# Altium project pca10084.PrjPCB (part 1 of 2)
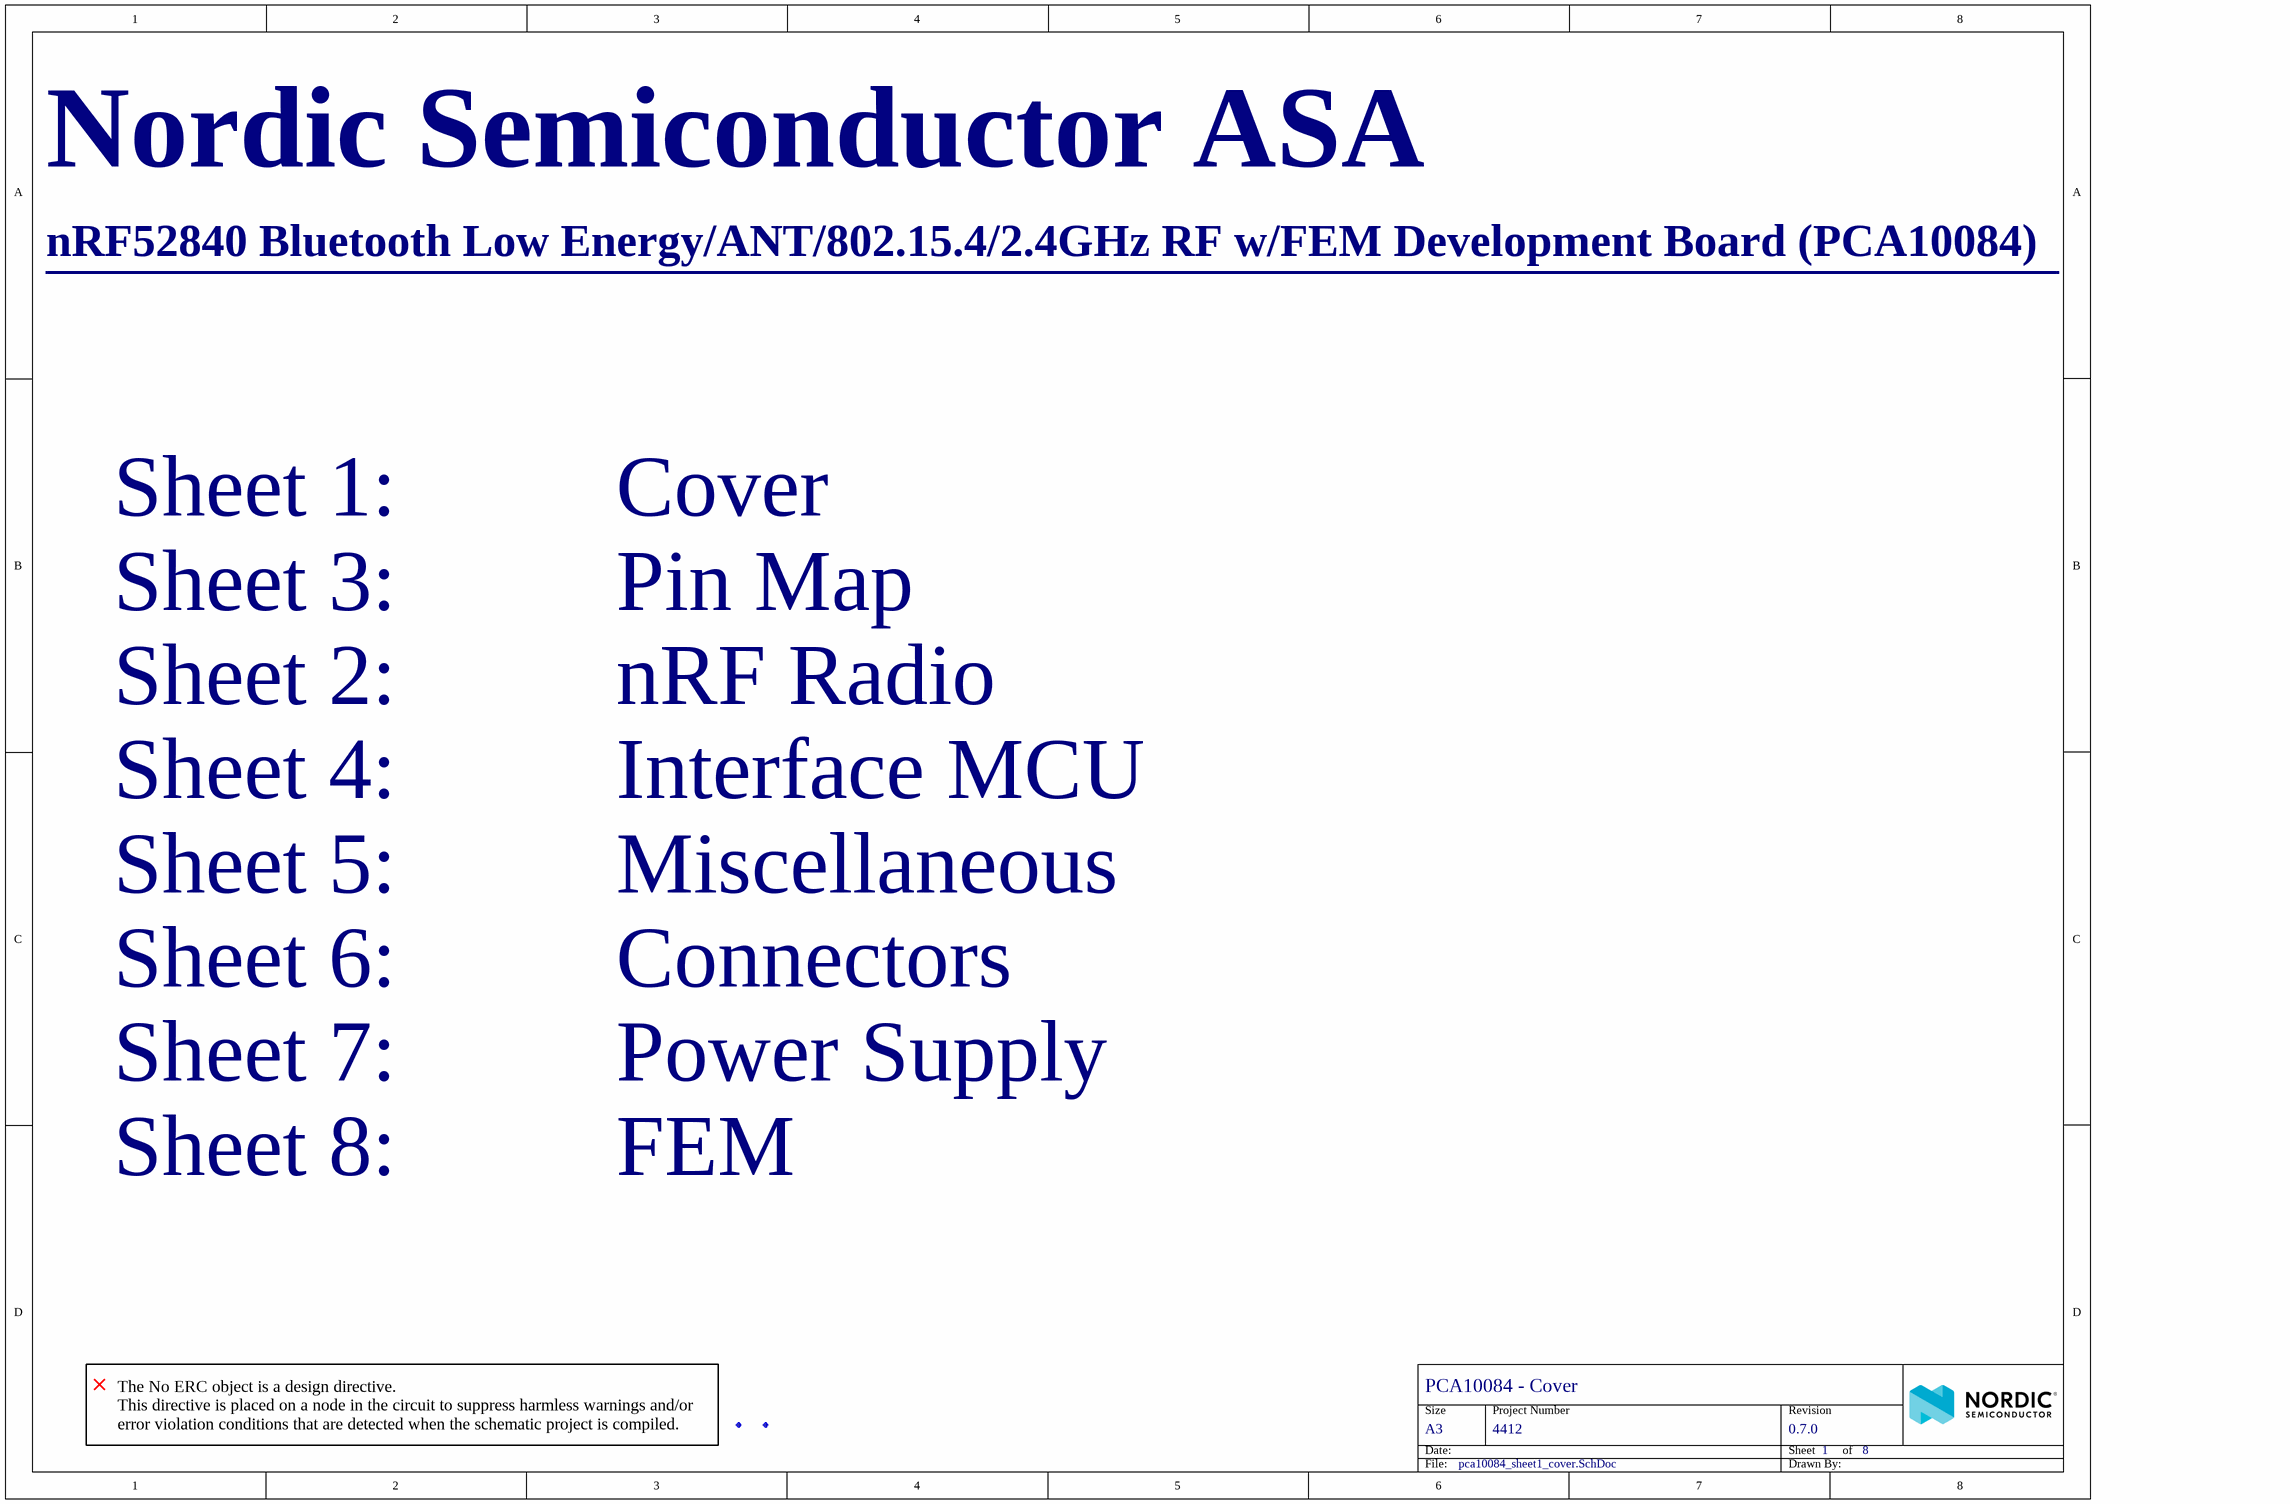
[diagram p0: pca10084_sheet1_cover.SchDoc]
Author: GETR; BoardThickness: 1.6mm; BoardTitle: nRF52840 with SkY66112-11; NrOfLayers: 4; Organization: Nordic Semiconductor; PCAName: PCA10084; PCBNumber: 400339; PCBRevision: 0093GETR; PCBStackup: 4001; ProjectName: Key Customer Support; ProjectNumber: 4412; Revision: 0.7.0; SilkscreenColor: White; SoldermaskColor: Blue; SurfaceFinish: Gold
8 sheets, 403 parts. Net scope: flat (ports and power ports of the same name join across sheets).
Board files: 400339.PcbDoc, 400339_panel.PcbDoc
Sheets:
  pca10084_sheet1_cover.SchDoc
  pca10084_sheet2_nrf52840_mcu.SchDoc
  pca10084_sheet3_pin_map.SchDoc
  pca10084_sheet4_interface_mcu.SchDoc
  pca10084_sheet5_misc.SchDoc
  pca10084_sheet6_connectors.SchDoc
  pca10084_sheet7_power_supply.SchDoc
  pca10084_sheet8_skyworks.SchDoc

## Sheet pca10084_sheet1_cover.SchDoc: PCA10084 - Cover
size A3; Organization: Nordic Semiconductor; DocumentNumber: 1; Revision: 0.7.0; SheetNumber: 1; SheetTotal: 8; Author: GETR; CompanyName: Nordic Semiconductor; DrawnBy: GETR

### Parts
Fid1  Fiducial mark  [Fiducial]  (value not drawn)  (no BOM)
Fid2  Fiducial mark  [Fiducial]  (value not drawn)  (no BOM)

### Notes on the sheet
- Nordic Semiconductor ASA
- nRF52840 Bluetooth Low Energy/ANT/802.15.4/2.4GHz RF w/FEM Development Board (PCA10084)
- __________________________________________________________________
- Sheet 1:          Cover
- Sheet 3:          Pin Map
- Sheet 2:          nRF Radio
- Sheet 4:          Interface MCU
- Sheet 5:          Miscellaneous
- Sheet 6:          Connectors
- Sheet 7:          Power Supply
- Sheet 8:          FEM
- (near Fid1) The No ERC object is a design directive.
  This directive is placed on a node in the circuit to suppress harmless warnings and/or error violation conditions that are detected when the schematic project is compiled.

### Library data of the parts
Fid1 Fid2 = Fid-Mark: Artikkelnr Noca: N.A.

## Sheet pca10084_sheet2_nrf52840_mcu.SchDoc: PCA10084 - nRF52840 MCU
size A3; Organization: Nordic Semiconductor; DocumentNumber: 2; Revision: 0.7.0; SheetNumber: 2; SheetTotal: 8; Author: GETR; CompanyName: Nordic Semiconductor; DrawnBy: GETR
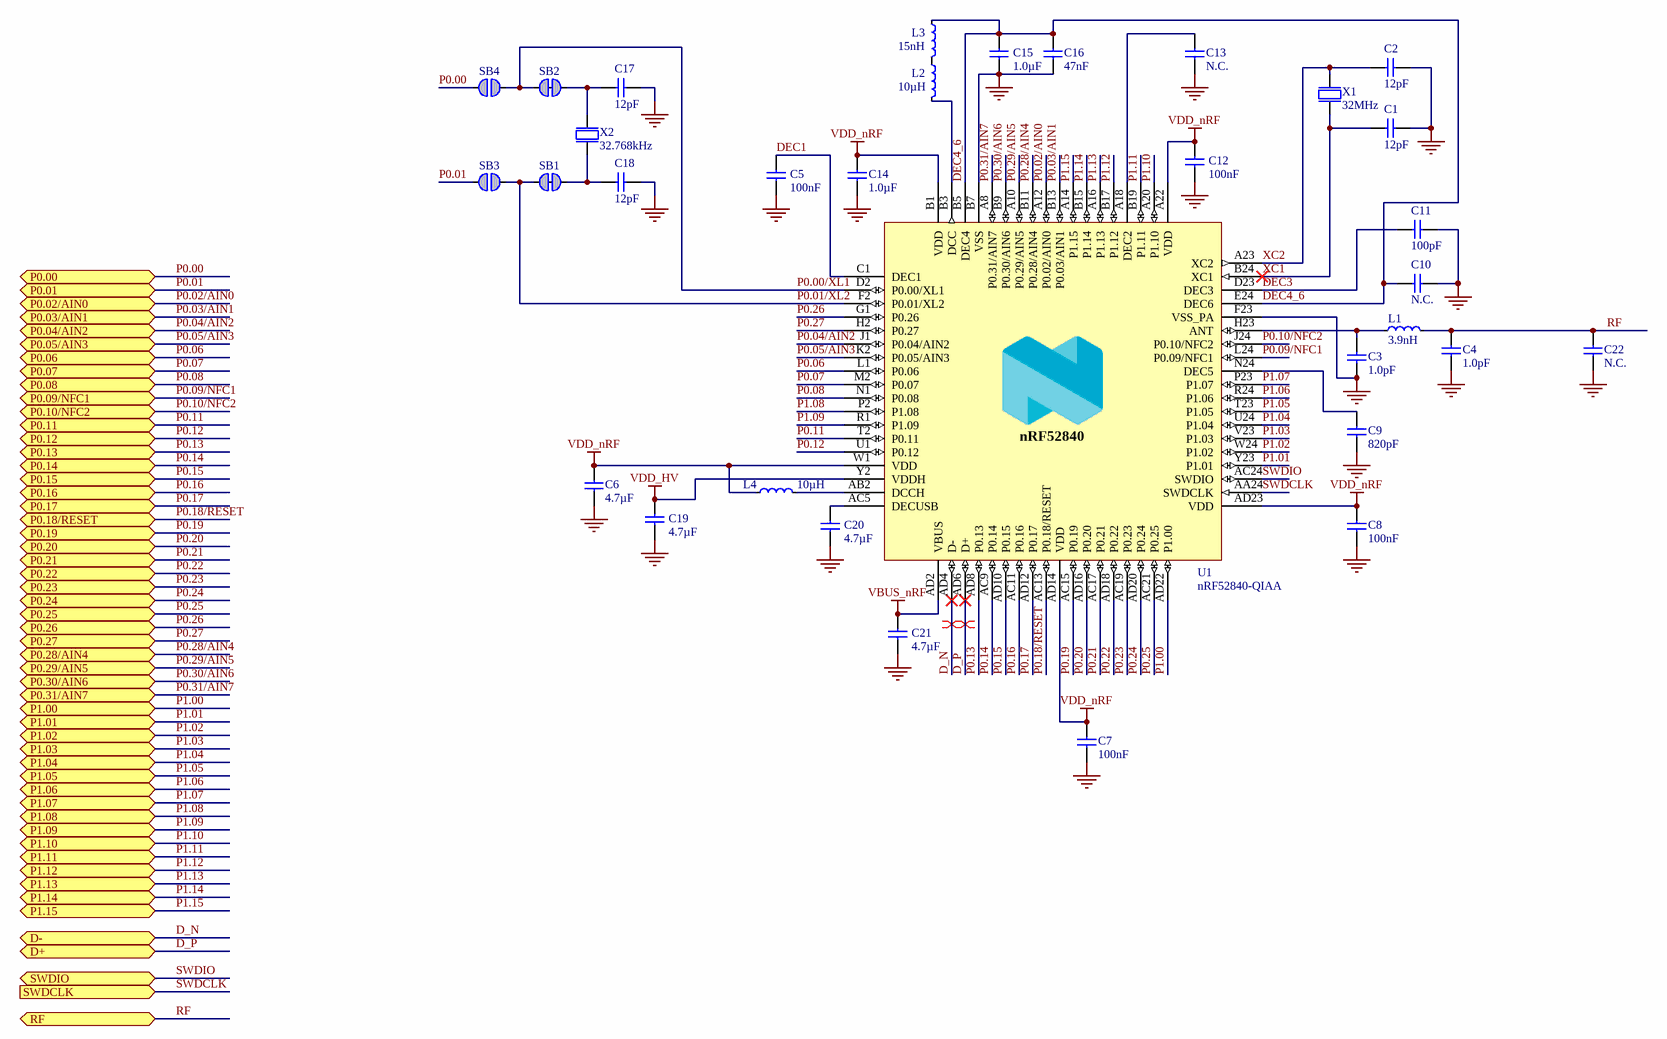
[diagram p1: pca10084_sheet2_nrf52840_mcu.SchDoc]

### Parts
C1  12pF  [CAPC1005X04L]
C2  12pF  [CAPC1005X04L]
C3  1.0pF  [CAPC1005X04L]
C4  1.0pF  [CAPC1005X04L]
C5  100nF  [CAPC1005X04L]
C6  4.7µF  [CAPC1608X06L]
C7  100nF  [CAPC1005X04L]
C8  100nF  [CAPC1005X04L]
C9  820pF  [CAPC1005X04L]
C10  N.C.  [CAPC1005X04L]
C11  100pF  [CAPC1005X04L]
C12  100nF  [CAPC1005X04L]
C13  N.C.  [CAPC1005X04L]
C14  1.0µF  [CAPC1608X06L]
C15  1.0µF  [CAPC1608X06L]
C16  47nF  [CAPC1005X04L]
C17  12pF  [CAPC1005X04L]
C18  12pF  [CAPC1005X04L]
C19  4.7µF  [CAPC1608X06L]
C20  4.7µF  [CAPC1608X06L]
C21  4.7µF  [CAPC1608X06L]
C22  N.C.  [CAPC1005X04L]
L1  3.9nH  [INDC1005X04L]
L2  10µH  [INDC1608X06L]
L3  15nH  [INDC1005X04L]
L4  10µH  [INDC1608X06L]
SB1  Solderbridge  [Solderbridge_Shorted]  (value not drawn)  (net tie, no BOM)
SB2  Solderbridge  [Solderbridge_Shorted]  (value not drawn)  (net tie, no BOM)
SB3  Solderbridge  [Solderbridge]  (value not drawn)  (no BOM)
SB4  Solderbridge  [Solderbridge]  (value not drawn)  (no BOM)
U1  nRF52840-QIAA  [AQFN50P700X700X85_HS-74N]
X1  32MHz  [BT-XTAL_2016]
X2  32.768kHz  [XTAL_3215]

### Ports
D+ (bidir), D- (bidir), P0.00 (bidir), P0.01 (bidir), P0.02/AIN0 (bidir), P0.03/AIN1 (bidir), P0.04/AIN2 (bidir), P0.05/AIN3 (bidir), P0.06 (bidir), P0.07 (bidir), P0.08 (bidir), P0.09/NFC1 (bidir), P0.10/NFC2 (bidir), P0.11 (bidir), P0.12 (bidir), P0.13 (bidir), P0.14 (bidir), P0.15 (bidir), P0.16 (bidir), P0.17 (bidir), P0.18/RESET (bidir), P0.19 (bidir), P0.20 (bidir), P0.21 (bidir), P0.22 (bidir), P0.23 (bidir), P0.24 (bidir), P0.25 (bidir), P0.26 (bidir), P0.27 (bidir), P0.28/AIN4 (bidir), P0.29/AIN5 (bidir), P0.30/AIN6 (bidir), P0.31/AIN7 (bidir), P1.00 (bidir), P1.01 (bidir), P1.02 (bidir), P1.03 (bidir), P1.04 (bidir), P1.05 (bidir), P1.06 (bidir), P1.07 (bidir), P1.08 (bidir), P1.09 (bidir), P1.10 (bidir), P1.11 (bidir), P1.12 (bidir), P1.13 (bidir), P1.14 (bidir), P1.15 (bidir), RF (bidir), SWDCLK (in), SWDIO (bidir)

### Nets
GND: C1.2 C2.2 C3.1 C4.1 C5.2 C6.2 C7.2 C8.2 C9.2 C10.1 C11.2 C12.2 C13.2 C14.2 C15.1 C16.2 C17.1 C18.1 C19.2 C20.2 C21.2 C22.2 U1.74(GND) U1.B7(VSS) U1.F23(VSS_PA) X1.2(GND) X1.4(GND)
VBUS_nRF: C21.1 U1.AD2(VBUS)
VDD_HV: C19.1 U1.Y2(VDDH)
VDD_nRF: C6.1 C7.1 C8.1 C12.1 C14.1 L4.1 U1.A22(VDD) U1.AD14(VDD) U1.AD23(VDD) U1.B1(VDD) U1.W1(VDD)
D_N: U1.AD4(D-) ; port D-
D_P: U1.AD6(D+) ; port D+
DEC1: C5.1 U1.C1(DEC1)
DEC3: C11.1 U1.D23(DEC3)
DEC4_6: C10.2 C15.2 C16.1 L3.1 U1.B5(DEC4) U1.E24(DEC6)
P0.00: SB4.2 ; port P0.00
P0.00/XL1: SB2.2 SB4.1 U1.D2(P0.00/XL1)
P0.01: SB3.2 ; port P0.01
P0.01/XL2: SB1.2 SB3.1 U1.F2(P0.01/XL2)
P0.02/AIN0: U1.A12(P0.02/AIN0) ; port P0.02/AIN0
P0.03/AIN1: U1.B13(P0.03/AIN1) ; port P0.03/AIN1
P0.04/AIN2: U1.J1(P0.04/AIN2) ; port P0.04/AIN2
P0.05/AIN3: U1.K2(P0.05/AIN3) ; port P0.05/AIN3
P0.06: U1.L1(P0.06) ; port P0.06
P0.07: U1.M2(P0.07) ; port P0.07
P0.08: U1.N1(P0.08) ; port P0.08
P0.09/NFC1: U1.L24(P0.09/NFC1) ; port P0.09/NFC1
P0.10/NFC2: U1.J24(P0.10/NFC2) ; port P0.10/NFC2
P0.11: U1.T2(P0.11) ; port P0.11
P0.12: U1.U1(P0.12) ; port P0.12
P0.13: U1.AD8(P0.13) ; port P0.13
P0.14: U1.AC9(P0.14) ; port P0.14
P0.15: U1.AD10(P0.15) ; port P0.15
P0.16: U1.AC11(P0.16) ; port P0.16
P0.17: U1.AD12(P0.17) ; port P0.17
P0.18/RESET: U1.AC13(P0.18/RESET) ; port P0.18/RESET
P0.19: U1.AC15(P0.19) ; port P0.19
P0.20: U1.AD16(P0.20) ; port P0.20
P0.21: U1.AC17(P0.21) ; port P0.21
P0.22: U1.AD18(P0.22) ; port P0.22
P0.23: U1.AC19(P0.23) ; port P0.23
P0.24: U1.AD20(P0.24) ; port P0.24
P0.25: U1.AC21(P0.25) ; port P0.25
P0.26: U1.G1(P0.26) ; port P0.26
P0.27: U1.H2(P0.27) ; port P0.27
P0.28/AIN4: U1.B11(P0.28/AIN4) ; port P0.28/AIN4
P0.29/AIN5: U1.A10(P0.29/AIN5) ; port P0.29/AIN5
P0.30/AIN6: U1.B9(P0.30/AIN6) ; port P0.30/AIN6
P0.31/AIN7: U1.A8(P0.31/AIN7) ; port P0.31/AIN7
P1.00: U1.AD22(P1.00) ; port P1.00
P1.01: U1.Y23(P1.01) ; port P1.01
P1.02: U1.W24(P1.02) ; port P1.02
P1.03: U1.V23(P1.03) ; port P1.03
P1.04: U1.U24(P1.04) ; port P1.04
P1.05: U1.T23(P1.05) ; port P1.05
P1.06: U1.R24(P1.06) ; port P1.06
P1.07: U1.P23(P1.07) ; port P1.07
P1.08: U1.P2(P1.08) ; port P1.08
P1.09: U1.R1(P1.09) ; port P1.09
P1.10: U1.A20(P1.10) ; port P1.10
P1.11: U1.B19(P1.11) ; port P1.11
P1.12: U1.B17(P1.12) ; port P1.12
P1.13: U1.A16(P1.13) ; port P1.13
P1.14: U1.B15(P1.14) ; port P1.14
P1.15: U1.A14(P1.15) ; port P1.15
RF: C4.2 C22.1 L1.2 ; port RF
SWDCLK: U1.AA24(SWDCLK) ; port SWDCLK
SWDIO: U1.AC24(SWDIO) ; port SWDIO
XC1: C1.1 U1.B24(XC1) X1.1(inp)
XC2: C2.1 U1.A23(XC2) X1.3(out)
NetC3_2: C3.2 L1.1 U1.H23(ANT)
NetC9_1: C9.1 U1.N24(DEC5)
NetC13_1: C13.1 U1.A18(DEC2)
NetC17_2: C17.2 SB2.1 X2.1(inp)
NetC18_2: C18.2 SB1.1 X2.2(out)
NetC20_1: C20.1 U1.AC5(DECUSB)
NetL2_1: L2.1 L3.2
NetL2_2: L2.2 U1.B3(DCC)
NetL4_2: L4.2 U1.AB2(DCCH)

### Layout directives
differential pair: D_N, D_P

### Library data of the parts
C1 C2 C17 C18 = C0402-12p: Capacitor, NP0, ±2%; Part number IPS: 00000002398; Note: 50V; Artikkelnr Noca: 20029159
C3 C4 = C0402-1.0p: Capacitor, NP0, ±0.1pF; Part number IPS: N.A.; Note: 50V; Artikkelnr Noca: 20029140
C5 C7 C8 C12 = C0402-100n: Capacitor, X7R, ±10%; Part number IPS: 00000005296; Note: 16V; Artikkelnr Noca: 20039200
C6 C20 = C0603-4µ7-6.3V-X7R: Capacitor, X7R, ±10%; Manufacturer: Samsung; Manufacturer Part Number: CL10B475KQ8NQNC; Part number IPS: N.A.; Note: 6.3V; Artikkelnr Noca: 20039473
C9 = C0402-820p: Capacitor, NP0, ±5%; Part number IPS: N.A.; Note: 50V; Artikkelnr Noca: 20029219
C10 C13 = C0402-N.C.: Not mounted; Note: Chip Cap; Assembly: Not mounted; Artikkelnr Noca: N.A.
C11 = C0402-100p: Capacitor, NP0, ±5%; Part number IPS: 00000002361; Note: 50V; Artikkelnr Noca: 20029135
C14 C15 = C0603-1µ0: Capacitor, X7R, ±10%; Part number IPS: 00000000616; Note: 16V; Artikkelnr Noca: 20039282
C16 = C0402-47n: Capacitor, X7R, ±10%; Part number IPS: N.A.; Note: Chip Cap 10%; Artikkelnr Noca: 20039389
C19 C21 = C0603-4µ7-10V-X7S: Capacitor, X7S, ±10%; Part number IPS: N.A.; Note: 10V; Artikkelnr Noca: 20030013
C22 = C0402-N.C.: Not mounted; Note: Chip Cap; Artikkelnr Noca: N.A.; Assembly: Not mounted
L1 = L0402-3n9: Inductor, 170mA, ±0.1nH; Manufacturer: Murata; Manufacturer Part Number: LQP15MN3N9B02D; Part number IPS: 00000007793; Note: High frequency chip inductor ±5%; Artikkelnr Noca: 33029151
L2 L4 = L0603-10µ: Inductor, 80mA, ±10%; Manufacturer: Taiyo Yuden; Manufacturer Part Number: LBMF1608T100K; Part number IPS: 00000007794; Note: LBMF1608T100K 10µH 80mA 0603; Artikkelnr Noca: 33029314
L3 = L0402-15n: Inductor, 320mA, ±5%; Manufacturer: Taiyo Yuden; Manufacturer Part Number: HK100515NJ-T; Part number IPS: 00000001262; Note: High frequency chip inductor ±10%; Artikkelnr Noca: 33029323
SB1 SB2 = Solderbridge Shorted: Shorted Solderbridge; Artikkelnr Noca: N.A.
SB3 SB4 = Solderbridge: Artikkelnr Noca: N.A.
U1 = nRF52840-QIAAC0: Multi-protocol Bluetooth Low Energy, IEEE 802.15.4, ANT and 2.4GHz proprietary system-on-chip; Manufacturer: Nordic Semiconductor; Part number IPS: N.A.; Artikkelnr Noca: 15079380
X1 = XTAL_SMD2016_32MHz_8pF_Golledge: XTAL SMD 2016, 32MHz, Cl=8pF, Tol: ±10ppm, Stab: ±15ppm; Manufacturer Part Number: MP06003; Part number IPS: N.A.; Note: XTAL SMD 32.000MHz; Artikkelnr Noca: 22010050
X2 = XTAL_SMD3215_32.768kHz_9pF_NDK: XTAL SMD 3215, 32.768kHz, 9pF, ±20ppm; Manufacturer: NDK; Manufacturer Part Number: NX3215SA-32.768K-STD-MUA-9; Part number IPS: N.A.; Note: XTAL SMD 32.768kHz; Artikkelnr Noca: 22010049

## Sheet pca10084_sheet3_pin_map.SchDoc: PCA10084 - Pin Map
size A3; Organization: Nordic Semiconductor; DocumentNumber: 3; Revision: 0.7.0; SheetNumber: 3; SheetTotal: 8; Author: GETR; CompanyName: Nordic Semiconductor; DrawnBy: GETR
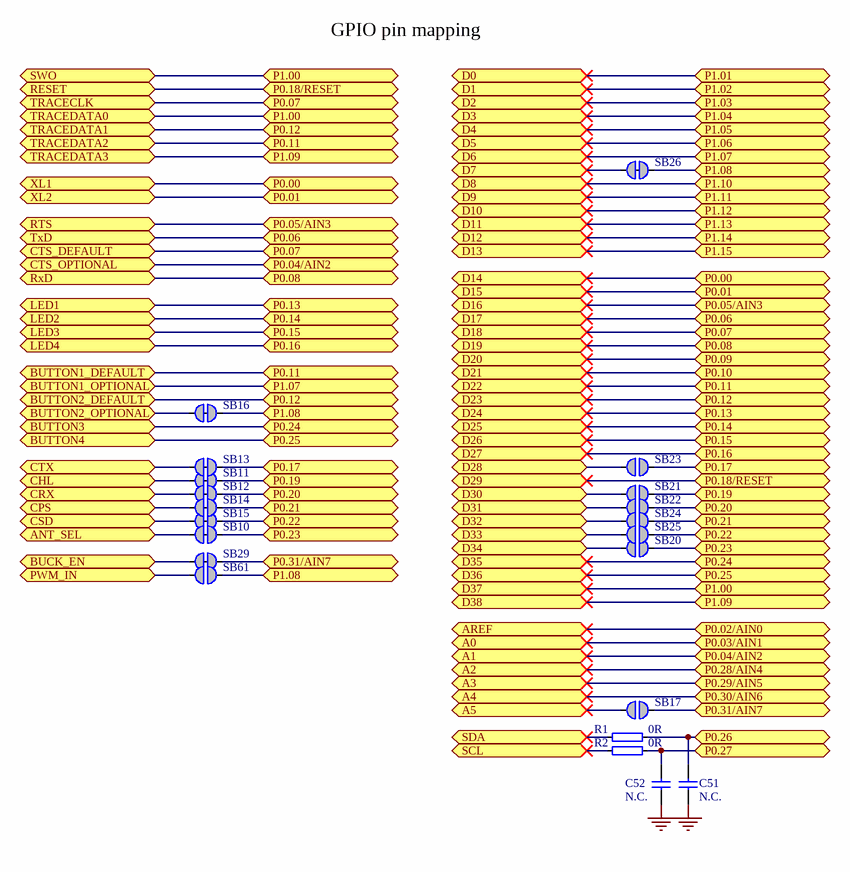
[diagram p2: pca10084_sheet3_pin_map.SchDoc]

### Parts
C51  N.C.  [CAPC1005X04L]
C52  N.C.  [CAPC1005X04L]
R1  0R  [RESC1005X04L]
R2  0R  [RESC1005X04L]
SB10  Solderbridge  [Solderbridge_Shorted]  (value not drawn)  (net tie, no BOM)
SB11  Solderbridge  [Solderbridge_Shorted]  (value not drawn)  (net tie, no BOM)
SB12  Solderbridge  [Solderbridge_Shorted]  (value not drawn)  (net tie, no BOM)
SB13  Solderbridge  [Solderbridge_Shorted]  (value not drawn)  (net tie, no BOM)
SB14  Solderbridge  [Solderbridge_Shorted]  (value not drawn)  (net tie, no BOM)
SB15  Solderbridge  [Solderbridge_Shorted]  (value not drawn)  (net tie, no BOM)
SB16  Solderbridge  [Solderbridge_Shorted]  (value not drawn)  (net tie, no BOM)
SB17  Solderbridge  [Solderbridge]  (value not drawn)  (no BOM)
SB20  Solderbridge  [Solderbridge]  (value not drawn)  (no BOM)
SB21  Solderbridge  [Solderbridge]  (value not drawn)  (no BOM)
SB22  Solderbridge  [Solderbridge]  (value not drawn)  (no BOM)
SB23  Solderbridge  [Solderbridge]  (value not drawn)  (no BOM)
SB24  Solderbridge  [Solderbridge]  (value not drawn)  (no BOM)
SB25  Solderbridge  [Solderbridge]  (value not drawn)  (no BOM)
SB26  Solderbridge  [Solderbridge_Shorted]  (value not drawn)  (net tie, no BOM)
SB29  Solderbridge  [Solderbridge_Shorted]  (value not drawn)  (net tie, no BOM)
SB61  Solderbridge  [Solderbridge]  (value not drawn)  (no BOM)

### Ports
A0 (bidir), A1 (bidir), A2 (bidir), A3 (bidir), A4 (bidir), A5 (bidir), ANT_SEL (bidir), AREF (bidir), BUCK_EN (bidir), BUTTON1_DEFAULT (bidir), BUTTON1_OPTIONAL (bidir), BUTTON2_DEFAULT (bidir), BUTTON2_OPTIONAL (bidir), BUTTON3 (bidir), BUTTON4 (bidir), CHL (bidir), CPS (bidir), CRX (bidir), CSD (bidir), CTS_DEFAULT (bidir), CTS_OPTIONAL (bidir), CTX (bidir), D0 (bidir), D1 (bidir), D2 (bidir), D3 (bidir), D4 (bidir), D5 (bidir), D6 (bidir), D7 (bidir), D8 (bidir), D9 (bidir), D10 (bidir), D11 (bidir), D12 (bidir), D13 (bidir), D14 (bidir), D15 (bidir), D16 (bidir), D17 (bidir), D18 (bidir), D19 (bidir), D20 (bidir), D21 (bidir), D22 (bidir), D23 (bidir), D24 (bidir), D25 (bidir), D26 (bidir), D27 (bidir), D28 (bidir), D29 (bidir), D30 (bidir), D31 (bidir), D32 (bidir), D33 (bidir), D34 (bidir), D35 (bidir), D36 (bidir), D37 (bidir), D38 (bidir), LED1 (bidir), LED2 (bidir), LED3 (bidir), LED4 (bidir), P0.00 (bidir), P0.01 (bidir), P0.02/AIN0 (bidir), P0.03/AIN1 (bidir), P0.04/AIN2 (bidir), P0.05/AIN3 (bidir), P0.06 (bidir), P0.07 (bidir), P0.08 (bidir), P0.09 (bidir), P0.10 (bidir), P0.11 (bidir), P0.12 (bidir), P0.13 (bidir), P0.14 (bidir), P0.15 (bidir), P0.16 (bidir), P0.17 (bidir), P0.18/RESET (bidir), P0.19 (bidir), P0.20 (bidir), P0.21 (bidir), P0.22 (bidir), P0.23 (bidir), P0.24 (bidir), P0.25 (bidir), P0.26 (bidir), P0.27 (bidir), P0.28/AIN4 (bidir), P0.29/AIN5 (bidir), P0.30/AIN6 (bidir), P0.31/AIN7 (bidir), P1.00 (bidir), P1.01 (bidir), P1.02 (bidir), P1.03 (bidir), P1.04 (bidir), P1.05 (bidir), P1.06 (bidir), P1.07 (bidir), P1.08 (bidir), P1.09 (bidir), P1.10 (bidir), P1.11 (bidir), P1.12 (bidir), P1.13 (bidir), P1.14 (bidir), P1.15 (bidir), PWM_IN (bidir), RESET (bidir), RTS (bidir), RxD (bidir), SCL (bidir), SDA (bidir), SWO (bidir), TRACECLK (bidir), TRACEDATA0 (bidir), TRACEDATA1 (bidir), TRACEDATA2 (bidir), TRACEDATA3 (bidir), TxD (bidir), XL1 (bidir), XL2 (bidir)

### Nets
GND: C51.1 C52.2
ANT_SEL: SB10.2 ; port ANT_SEL
BUCK_EN: SB29.2 ; port BUCK_EN
CHL: SB11.2 ; port CHL
CPS: SB14.2 ; port CPS
CRX: SB12.2 ; port CRX
CSD: SB15.2 ; port CSD
CTX: SB13.2 ; port CTX
P0.00: port P0.00, port XL1, port D14
P0.01: port P0.01, port XL2, port D15
P0.02/AIN0: port AREF, port P0.02/AIN0
P0.03/AIN1: port A0, port P0.03/AIN1
P0.04/AIN2: port P0.04/AIN2, port CTS_OPTIONAL, port A1
P0.05/AIN3: port RTS, port D16, port P0.05/AIN3
P0.06: port TxD, port P0.06, port D17
P0.07: port P0.07, port TRACECLK, port CTS_DEFAULT, port D18
P0.08: port RxD, port P0.08, port D19
P0.11: port TRACEDATA2, port P0.11, port BUTTON1_DEFAULT, port D22
P0.12: port TRACEDATA1, port P0.12, port BUTTON2_DEFAULT, port D23
P0.13: port P0.13, port LED1, port D24
P0.14: port P0.14, port LED2, port D25
P0.15: port P0.15, port LED3, port D26
P0.16: port P0.16, port LED4, port D27
P0.17: SB13.1 SB23.1 ; port P0.17
P0.18/RESET: port RESET, port P0.18/RESET, port D29
P0.19: SB11.1 SB21.1 ; port P0.19
P0.20: SB12.1 SB22.1 ; port P0.20
P0.21: SB14.1 SB24.1 ; port P0.21
P0.22: SB15.1 SB25.1 ; port P0.22
P0.23: SB10.1 SB20.1 ; port P0.23
P0.24: port P0.24, port BUTTON3, port D35
P0.25: port P0.25, port BUTTON4, port D36
P0.26: C51.2 R1.2 ; port P0.26
P0.27: C52.1 R2.2 ; port P0.27
P0.28/AIN4: port A2, port P0.28/AIN4
P0.29/AIN5: port A3, port P0.29/AIN5
P0.30/AIN6: port A4, port P0.30/AIN6
P0.31/AIN7: SB17.1 SB29.1 ; port P0.31/AIN7
P1.00: port TRACEDATA0, port SWO, port P1.00, port D37
P1.01: port P1.01, port D0
P1.02: port P1.02, port D1
P1.03: port P1.03, port D2
P1.04: port P1.04, port D3
P1.05: port P1.05, port D4
P1.06: port P1.06, port D5
P1.07: port P1.07, port BUTTON1_OPTIONAL, port D6
P1.08: SB16.1 SB26.1 SB61.1 ; port P1.08
P1.09: port TRACEDATA3, port P1.09, port D38
P1.10: port P1.10, port D8
P1.11: port P1.11, port D9
P1.12: port P1.12, port D10
P1.13: port P1.13, port D11
P1.14: port P1.14, port D12
P1.15: port P1.15, port D13
PWM_IN: SB61.2 ; port PWM_IN
SCL: R2.1 ; port SCL
SDA: R1.1 ; port SDA
NetP2_6: SB17.2 ; port A5
NetP3_8: SB26.2 ; port D7
NetP6_7: port D20, port P0.09
NetP6_8: port D21, port P0.10
NetP24_7: SB23.2 ; port D28
NetP24_9: SB21.2 ; port D30
NetP24_10: SB22.2 ; port D31
NetP24_11: SB24.2 ; port D32
NetP24_12: SB25.2 ; port D33
NetP24_13: SB20.2 ; port D34
NetSB16_2: SB16.2 ; port BUTTON2_OPTIONAL

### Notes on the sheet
- GPIO pin mapping

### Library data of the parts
C51 C52 = C0402-N.C.: Not mounted; Assembly: Not mounted; Note: Chip Cap; Artikkelnr Noca: N.A.
R1 R2 = R0402-0R: Resistor, ±5%, 0.063W; Part number IPS: N.A.; Note: Chip Res 5%; Artikkelnr Noca: 27049000
SB10-SB16 SB26 SB29 = Solderbridge Shorted: as SB1 on sheet pca10084_sheet2_nrf52840_mcu
SB17 SB20-SB25 SB61 = Solderbridge: Artikkelnr Noca: N.A.

## Sheet pca10084_sheet4_interface_mcu.SchDoc: PCA10084 - Interface MCU
size A3; Organization: Nordic Semiconductor; DocumentNumber: 4; Revision: 0.7.0; SheetNumber: 4; SheetTotal: 8; Author: GETR; CompanyName: Nordic Semiconductor; DrawnBy: GETR
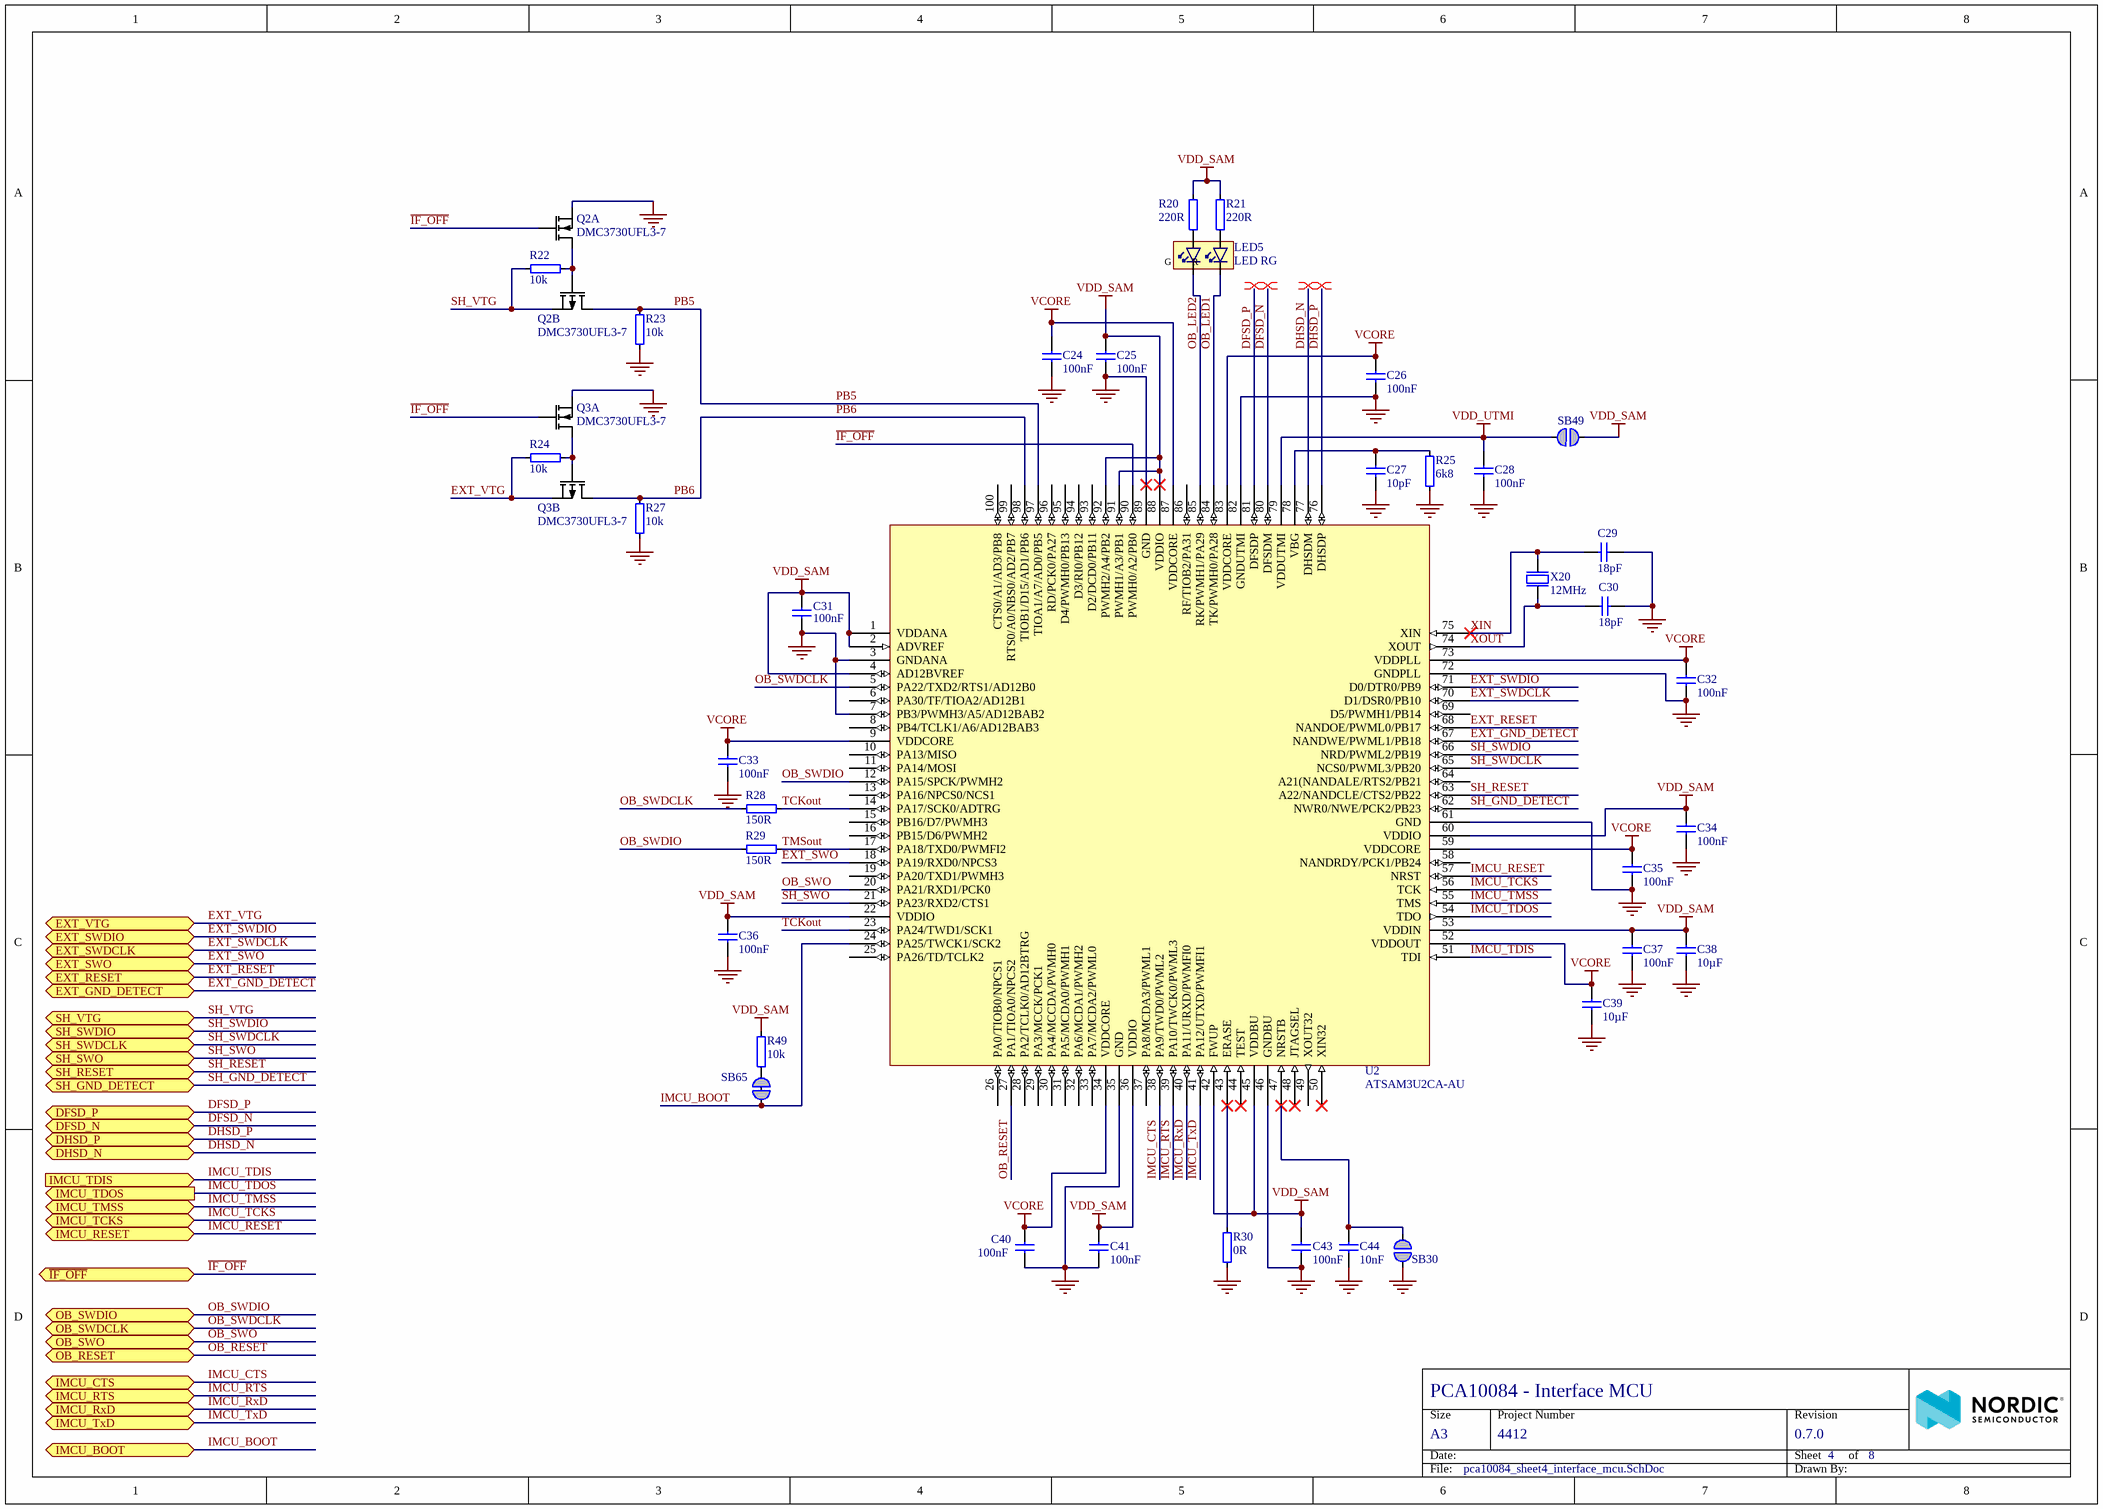
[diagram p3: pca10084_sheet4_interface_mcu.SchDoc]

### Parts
C24  100nF  [CAPC1005X04L]
C25  100nF  [CAPC1005X04L]
C26  100nF  [CAPC1005X04L]
C27  10pF  [CAPC1005X04L]
C28  100nF  [CAPC1005X04L]
C29  18pF  [CAPC1005X04L]
C30  18pF  [CAPC1005X04L]
C31  100nF  [CAPC1005X04L]
C32  100nF  [CAPC1005X04L]
C33  100nF  [CAPC1005X04L]
C34  100nF  [CAPC1005X04L]
C35  100nF  [CAPC1005X04L]
C36  100nF  [CAPC1005X04L]
C37  100nF  [CAPC1005X04L]
C38  10µF  [CAPC1608X06L]
C39  10µF  [CAPC1608X06L]
C40  100nF  [CAPC1005X04L]
C41  100nF  [CAPC1005X04L]
C43  100nF  [CAPC1005X04L]
C44  10nF  [CAPC1005X04L]
LED5  LED RG  [LED_DUAL_0606]
Q2  DMC3730UFL3-7  [DMC3730UFL3-7]  (parts A,B of 2)
Q3  DMC3730UFL3-7  [DMC3730UFL3-7]  (parts A,B of 2)
R20  220R  [RESC1005X04L]
R21  220R  [RESC1005X04L]
R22  10k  [RESC1005X04L]
R23  10k  [RESC1005X04L]
R24  10k  [RESC1005X04L]
R25  6k8  [RESC1005X04L]
R27  10k  [RESC1005X04L]
R28  150R  [RESC1005X04L]
R29  150R  [RESC1005X04L]
R30  0R  [RESC1005X04L]
R49  10k  [RESC1005X04L]
SB30  Solderbridge  [Solderbridge]  (value not drawn)  (no BOM)
SB49  Solderbridge  [Solderbridge]  (value not drawn)  (no BOM)
SB65  Solderbridge  [Solderbridge_Shorted]  (value not drawn)  (net tie, no BOM)
U2  ATSAM3U2CA-AU  [TSQFP50P1600X1600X160-100N]
X20  12MHz  [BT-XTAL_3225]

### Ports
DFSD_N (bidir), DFSD_P (bidir), DHSD_N (bidir), DHSD_P (bidir), EXT_GND_DETECT (bidir), EXT_RESET (bidir), EXT_SWDCLK (bidir), EXT_SWDIO (bidir), EXT_SWO (bidir), EXT_VTG (bidir), IMCU_BOOT (bidir), IMCU_CTS (bidir), IMCU_RESET (bidir), IMCU_RTS (bidir), IMCU_RxD (bidir), IMCU_TCKS (bidir), IMCU_TDIS (in), IMCU_TDOS (out), IMCU_TMSS (bidir), IMCU_TxD (bidir), OB_RESET (bidir), OB_SWDCLK (bidir), OB_SWDIO (bidir), OB_SWO (bidir), SH_GND_DETECT (bidir), SH_RESET (bidir), SH_SWDCLK (bidir), SH_SWDIO (bidir), SH_SWO (bidir), SH_VTG (bidir), ~{IF_OFF} (bidir)

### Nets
GND: C24.1 C25.1 C26.1 C27.1 C28.1 C29.2 C30.2 C31.1 C32.2 C33.1 C34.1 C35.1 C36.1 C37.1 C38.1 C39.1 C40.1 C41.1 C43.1 C44.1 Q2.1(S1) Q3.1(S1) R23.1 R25.1 R27.1 R30.1 SB30.2 U2.3(GNDANA) U2.7(PB3/PWMH3/A5/AD12BAB2) U2.35(GND) U2.46(GNDBU) U2.61(GND) U2.72(GNDPLL) U2.82(GNDUTMI) U2.89(GND) X20.2(GND) X20.4(GND)
VCORE: C24.2 C26.2 C32.1 C33.2 C35.2 C39.2 C40.2 U2.9(VDDCORE) U2.34(VDDCORE) U2.52(VDDOUT) U2.59(VDDCORE) U2.73(VDDPLL) U2.83(VDDCORE) U2.87(VDDCORE)
VDD_SAM: C25.2 C31.2 C34.2 C36.2 C37.2 C38.2 C41.2 C43.2 R20.2 R21.2 R49.2 SB49.1 U2.1(VDDANA) U2.2(ADVREF) U2.4(AD12BVREF) U2.22(VDDIO) U2.36(VDDIO) U2.42(FWUP) U2.45(VDDBU) U2.53(VDDIN) U2.60(VDDIO) U2.88(VDDIO) U2.91(PWMH1/A3/PB1) U2.92(PWMH2/A4/PB2)
VDD_UTMI: C28.2 SB49.2 U2.79(VDDUTMI)
DFSD_N: U2.80(DFSDM) ; port DFSD_N
DFSD_P: U2.81(DFSDP) ; port DFSD_P
DHSD_N: U2.77(DHSDM) ; port DHSD_N
DHSD_P: U2.76(DHSDP) ; port DHSD_P
EXT_GND_DETECT: U2.67(NANDWE/PWML1/PB18) ; port EXT_GND_DETECT
EXT_RESET: U2.68(NANDOE/PWML0/PB17) ; port EXT_RESET
EXT_SWDCLK: U2.70(D1/DSR0/PB10) ; port EXT_SWDCLK
EXT_SWDIO: U2.71(D0/DTR0/PB9) ; port EXT_SWDIO
EXT_SWO: U2.18(PA19/RXD0/NPCS3) ; port EXT_SWO
EXT_VTG: Q3.4(S2) R24.1 ; port EXT_VTG
~{IF_OFF}: Q2.2(G1) Q3.2(G1) U2.90(PWMH0/A2/PB0) ; port ~{IF_OFF}
IMCU_BOOT: SB65.1 U2.24(PA25/TWCK1/SCK2) ; port IMCU_BOOT
IMCU_CTS: U2.38(PA9/TWD0/PWML2) ; port IMCU_CTS
IMCU_RESET: U2.57(NRST) ; port IMCU_RESET
IMCU_RTS: U2.39(PA10/TWCK0/PWML3) ; port IMCU_RTS
IMCU_RxD: U2.40(PA11/URXD/PWMFI0) ; port IMCU_RxD
IMCU_TCKS: U2.56(TCK) ; port IMCU_TCKS
IMCU_TDIS: U2.51(TDI) ; port IMCU_TDIS
IMCU_TDOS: U2.54(TDO) ; port IMCU_TDOS
IMCU_TMSS: U2.55(TMS) ; port IMCU_TMSS
IMCU_TxD: U2.41(PA12/UTXD/PWMFI1) ; port IMCU_TxD
OB_LED1: LED5.4(C1) U2.84(TK/PWMH0/PA28)
OB_LED2: LED5.3(C2) U2.85(RK/PWMH1/PA29)
OB_RESET: U2.27(PA1/TIOA0/NPCS2) ; port OB_RESET
OB_SWDCLK: R28.2 U2.5(PA22/TXD2/RTS1/AD12B0) ; port OB_SWDCLK
OB_SWDIO: R29.2 U2.12(PA15/SPCK/PWMH2) ; port OB_SWDIO
OB_SWO: U2.20(PA21/RXD1/PCK0) ; port OB_SWO
PB5: Q2.3(D2) R23.2 U2.97(TIOA1/A7/AD0/PB5)
PB6: Q3.3(D2) R27.2 U2.98(TIOB1/D15/AD1/PB6)
SH_GND_DETECT: U2.62(NWR0/NWE/PCK2/PB23) ; port SH_GND_DETECT
SH_RESET: U2.63(A22/NANDCLE/CTS2/PB22) ; port SH_RESET
SH_SWDCLK: U2.65(NCS0/PWML3/PB20) ; port SH_SWDCLK
SH_SWDIO: U2.66(NRD/PWML2/PB19) ; port SH_SWDIO
SH_SWO: U2.21(PA23/RXD2/CTS1) ; port SH_SWO
SH_VTG: Q2.4(S2) R22.1 ; port SH_VTG
TCKout: R28.1 U2.14(PA17/SCK0/ADTRG) U2.23(PA24/TWD1/SCK1)
TMSout: R29.1 U2.17(PA18/TXD0/PWMFI2)
XIN: C29.1 U2.75(XIN) X20.3(out)
XOUT: C30.1 U2.74(XOUT) X20.1(inp)
NetC27_2: C27.2 R25.2 U2.78(VBG)
NetC44_2: C44.2 SB30.1 U2.47(NRSTB)
NetLED5_1: LED5.1(A2) R20.1
NetLED5_2: LED5.2(A1) R21.1
NetQ2_5: Q2.5(G2) Q2.6(D1) R22.2
NetQ3_5: Q3.5(G2) Q3.6(D1) R24.2
NetR30_2: R30.2 U2.43(ERASE)
NetR49_1: R49.1 SB65.2

Not connected (* = marked no-connect by the designer): U2 6(PA30/TF/TIOA2/AD12B1) 8(PB4/TCLK1/A6/AD12BAB3) 10(PA13/MISO) 11(PA14/MOSI) 13(PA16/NPCS0/NCS1) 15(PB16/D7/PWMH3) 16(PB15/D6/PWMH2) 19(PA20/TXD1/PWMH3) 25(PA26/TD/TCLK2) 26(PA0/TIOB0/NPCS1) 28(PA2/TCLK0/AD12BTRG) 29(PA3/MCCK/PCK1) 30(PA4/MCCDA/PWMH0) 31(PA5/MCDA0/PWMH1) 32(PA6/MCDA1/PWMH2) 33(PA7/MCDA2/PWML0) 37(PA8/MCDA3/PWML1) 44(TEST)* 48(JTAGSEL)* 49(XOUT32) 50(XIN32)* 58(NANDRDY/PCK1/PB24) 64(A21(NANDALE/RTS2/PB21) 69(D5/PWMH1/PB14) 86(RF/TIOB2/PA31) 93(D2/DCD0/PB11) 94(D3/RI0/PB12) 95(D4/PWMH0/PB13) 96(RD/PCK0/PA27) 99(RTS0/A0/NBS0/AD2/PB7) 100(CTS0/A1/AD3/PB8)

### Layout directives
differential pair: DFSD_N, DFSD_P, DHSD_N, DHSD_P

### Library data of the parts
C24-C26 C28 C31-C37 C40 C41 C43 = C0402-100n: as C5 on sheet pca10084_sheet2_nrf52840_mcu
C27 = C0402-10p: Capacitor, NP0, ±2%; Part number IPS: N.A.; Note: 50V; Artikkelnr Noca: 20029260
C29 C30 = C0402-18p: Capacitor, NP0, ±5%; Part number IPS: N.A.; Note: 50V; Artikkelnr Noca: 20029209
C38 C39 = C0603-10µ: Capacitor, X5R, ±20%; Part number IPS: 00000007785; Note: 6.3V; Artikkelnr Noca: 20039234
C44 = C0402-10n: Capacitor, X7R, ±10%; Part number IPS: 00000007784; Note: 16V; Artikkelnr Noca: 20039166
LED5 = LTST-C195KGJRKT: Ultra bright AlInGaP Bi-Color LED; Manufacturer: Lite-On Inc; Part number IPS: N.A.; Artikkelnr Noca: 13019145
Q2 Q3 = DMC3730UFL3-7: MOSFET N/P-CHA 30V 1.1A DFN1310; Manufacturer: Diodes Incorporated; Artikkelnr Noca: N.A.
R20 R21 = R0402-220: Resistor, ±1%, 0.063W; Part number IPS: N.A.; Note: Chip Res 1%; Artikkelnr Noca: 27049057
R22-R24 R27 R49 = R0402-10k: Resistor, ±1%, 0.063W; Part number IPS: 00000002093; Note: Chip Res 1%; Artikkelnr Noca: 27049097
R25 = R0402-6k8: Resistor, ±1%, 0.063W; Part number IPS: N.A.; Note: Chip Res 1%; Artikkelnr Noca: 27049093
R28 R29 = R0402-150: Resistor, ±1%, 0.063W; Part number IPS: N.A.; Note: Chip Res 1%; Artikkelnr Noca: 27049053
R30 = R0402-0R: as R1 on sheet pca10084_sheet3_pin_map
SB30 SB49 = Solderbridge: Artikkelnr Noca: N.A.
SB65 = Solderbridge Shorted: as SB1 on sheet pca10084_sheet2_nrf52840_mcu
U2 = ATSAM3U2CA-AU: IC MCU 32bit 128kB flash 100LQFP; Manufacturer: Atmel; Part number IPS: N.A.; Artikkelnr Noca: 15019073
X20 = XTAL_SMD3225_12MHz_18pF_TXC: XTAL SMD 3225, 12MHz, Cl=18pF, Tol: ±30ppm, Stab: ±30ppm; Manufacturer: TXC Corporation; Manufacturer Part Number: 7M-12.000MAAJ-T; Part number IPS: N.A.; Note: XTAL SMD 12.000MHz; Artikkelnr Noca: 22019166

## Sheet pca10084_sheet5_misc.SchDoc: PCA10084 - Miscellaneous
size A3; Organization: Nordic Semiconductor; DocumentNumber: 5; Revision: 0.7.0; SheetNumber: 5; SheetTotal: 8; Author: GETR; CompanyName: Nordic Semiconductor; DrawnBy: GETR
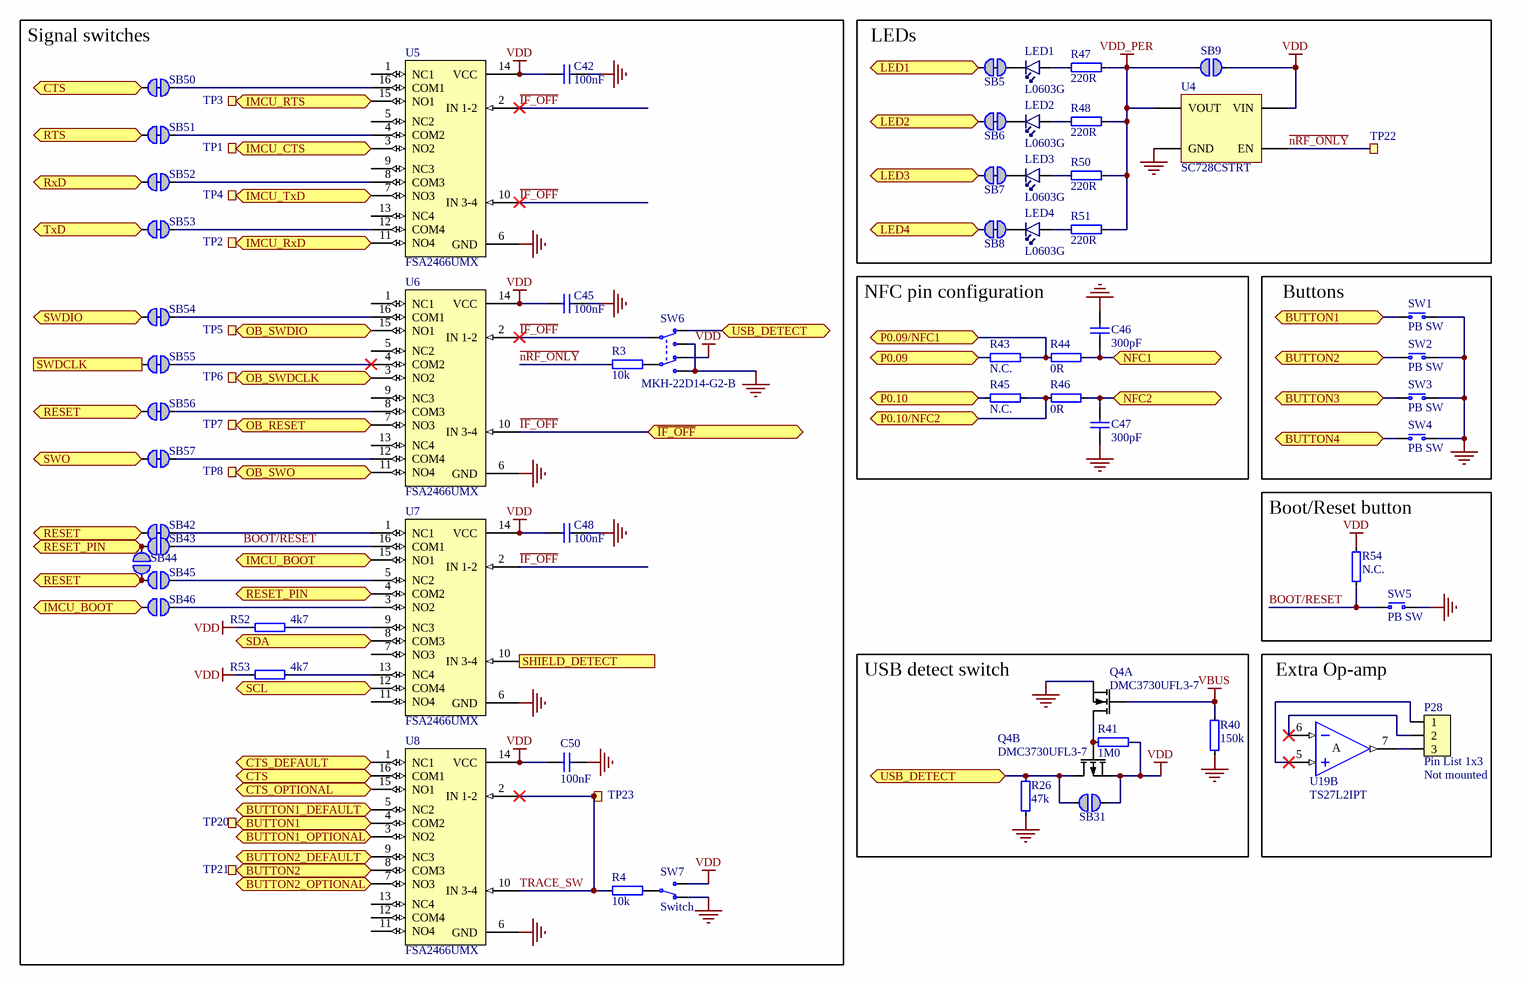
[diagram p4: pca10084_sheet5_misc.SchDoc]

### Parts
C42  100nF  [CAPC1005X04L]
C45  100nF  [CAPC1005X04L]
C46  300pF  [CAPC1005X04L]
C47  300pF  [CAPC1005X04L]
C48  100nF  [CAPC1005X04L]
C50  100nF  [CAPC1005X04L]
LED1  L0603G  [LED_0603_G]
LED2  L0603G  [LED_0603_G]
LED3  L0603G  [LED_0603_G]
LED4  L0603G  [LED_0603_G]
P28  Pin List 1x3  Assembly: Not mounted  [LIST_1x3-NC]
Q4  DMC3730UFL3-7  [DMC3730UFL3-7]  (parts A,B of 2)
R3  10k  [RESC1005X04L]
R4  10k  [RESC1005X04L]
R26  47k  [RESC1005X04L]
R40  150k  [RESC1005X04L]
R41  1M0  [RESC1005X04L]
R43  N.C.  [RESC1005X04L]
R44  0R  [RESC1005X04L]
R45  N.C.  [RESC1005X04L]
R46  0R  [RESC1005X04L]
R47  220R  [RESC1005X04L]
R48  220R  [RESC1005X04L]
R50  220R  [RESC1005X04L]
R51  220R  [RESC1005X04L]
R52  4k7  [RESC1005X04L]
R53  4k7  [RESC1005X04L]
R54  N.C.  [RESC1005X04L]
SB5  Solderbridge  [Solderbridge_Shorted]  (value not drawn)  (net tie, no BOM)
SB6  Solderbridge  [Solderbridge_Shorted]  (value not drawn)  (net tie, no BOM)
SB7  Solderbridge  [Solderbridge_Shorted]  (value not drawn)  (net tie, no BOM)
SB8  Solderbridge  [Solderbridge_Shorted]  (value not drawn)  (net tie, no BOM)
SB9  Solderbridge  [Solderbridge]  (value not drawn)  (no BOM)
SB31  Solderbridge  [Solderbridge]  (value not drawn)  (no BOM)
SB42  Solderbridge  [Solderbridge_Shorted]  (value not drawn)  (net tie, no BOM)
SB43  Solderbridge  [Solderbridge]  (value not drawn)  (no BOM)
SB44  Solderbridge  [Solderbridge]  (value not drawn)  (no BOM)
SB45  Solderbridge  [Solderbridge]  (value not drawn)  (no BOM)
SB46  Solderbridge  [Solderbridge]  (value not drawn)  (no BOM)
SB50  Solderbridge  [Solderbridge_Shorted]  (value not drawn)  (net tie, no BOM)
SB51  Solderbridge  [Solderbridge_Shorted]  (value not drawn)  (net tie, no BOM)
SB52  Solderbridge  [Solderbridge_Shorted]  (value not drawn)  (net tie, no BOM)
SB53  Solderbridge  [Solderbridge_Shorted]  (value not drawn)  (net tie, no BOM)
SB54  Solderbridge  [Solderbridge_Shorted]  (value not drawn)  (net tie, no BOM)
SB55  Solderbridge  [Solderbridge_Shorted]  (value not drawn)  (net tie, no BOM)
SB56  Solderbridge  [Solderbridge_Shorted]  (value not drawn)  (net tie, no BOM)
SB57  Solderbridge  [Solderbridge_Shorted]  (value not drawn)  (net tie, no BOM)
SW1  PB SW  [Switch-PB-6.2x6.3mm-SMD]
SW2  PB SW  [Switch-PB-6.2x6.3mm-SMD]
SW3  PB SW  [Switch-PB-6.2x6.3mm-SMD]
SW4  PB SW  [Switch-PB-6.2x6.3mm-SMD]
SW5  PB SW  [Switch-PB-6.2x6.3mm-SMD]
SW6  MKH-22D14-G2-B  [MKH-22D14-G2-B]
SW7  Switch  [CJS-120xA]
TP1  Ø1.0mm,SMD  [TP_SMD_Ø1.0mm]  (value not drawn)  (no BOM)
TP2  Ø1.0mm,SMD  [TP_SMD_Ø1.0mm]  (value not drawn)  (no BOM)
TP3  Ø1.0mm,SMD  [TP_SMD_Ø1.0mm]  (value not drawn)  (no BOM)
TP4  Ø1.0mm,SMD  [TP_SMD_Ø1.0mm]  (value not drawn)  (no BOM)
TP5  Ø1.0mm,SMD  [TP_SMD_Ø1.0mm]  (value not drawn)  (no BOM)
TP6  Ø1.0mm,SMD  [TP_SMD_Ø1.0mm]  (value not drawn)  (no BOM)
TP7  Ø1.0mm,SMD  [TP_SMD_Ø1.0mm]  (value not drawn)  (no BOM)
TP8  Ø1.0mm,SMD  [TP_SMD_Ø1.0mm]  (value not drawn)  (no BOM)
TP20  Ø1.0mm,SMD  [TP_SMD_Ø1.0mm]  (value not drawn)  (no BOM)
TP21  Ø1.0mm,SMD  [TP_SMD_Ø1.0mm]  (value not drawn)  (no BOM)
TP22  Ø1.0mm,SMD  [TP_SMD_Ø1.0mm]  (value not drawn)  (no BOM)
TP23  Ø1.0mm,SMD  [TP_SMD_Ø1.0mm]  (value not drawn)  (no BOM)
U4  SC728CSTRT  [BGA4C40P2X2_76X76X62]
U5  FSA2466UMX  [XQFN40P180X260X50-16N]
U6  FSA2466UMX  [XQFN40P180X260X50-16N]
U7  FSA2466UMX  [XQFN40P180X260X50-16N]
U8  FSA2466UMX  [XQFN40P180X260X50-16N]
U19  TS27L2IPT  [TSOP65P640X120-8N]  (part B of 2)

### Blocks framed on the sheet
Signal switches: C42 C45 C48 C50 R3 R4 R52 R53 SB42-SB46 SB50-SB57 SW6 SW7 TP1-TP8 TP20 TP21 TP23 U5-U8
LEDs: LED1-LED4 R47 R48 R50 R51 SB5-SB9 TP22 U4
NFC pin configuration: C46 C47 R43-R46
Buttons: SW1-SW4
Boot/Reset button: R54 SW5
USB detect switch: Q4 R26 R40 R41 SB31
Extra Op-amp: P28 U19

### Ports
BUTTON1 (bidir), BUTTON1_DEFAULT (bidir), BUTTON1_OPTIONAL (bidir), BUTTON2 (bidir), BUTTON2_DEFAULT (bidir), BUTTON2_OPTIONAL (bidir), BUTTON3 (bidir), BUTTON4 (bidir), CTS (bidir), CTS_DEFAULT (bidir), CTS_OPTIONAL (bidir), IMCU_BOOT (bidir), IMCU_CTS (bidir), IMCU_RTS (bidir), IMCU_RxD (bidir), IMCU_TxD (bidir), LED1 (bidir), LED2 (bidir), LED3 (bidir), LED4 (bidir), NFC1 (bidir), NFC2 (bidir), OB_RESET (bidir), OB_SWDCLK (bidir), OB_SWDIO (bidir), OB_SWO (bidir), P0.09 (bidir), P0.09/NFC1 (bidir), P0.10 (bidir), P0.10/NFC2 (bidir), RESET (bidir), RESET_PIN (bidir), RTS (bidir), RxD (bidir), SCL (bidir), SDA (bidir), SHIELD_DETECT (in), SWDCLK (out), SWDIO (bidir), SWO (bidir), TxD (bidir), USB_DETECT (bidir), ~{IF_OFF} (bidir)

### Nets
GND: C42.1 C45.1 C46.2 C47.1 C48.1 C50.1 Q4.1(S1) R26.2 R40.2 SW1.1(N.O) SW2.1(N.O) SW3.1(N.O) SW4.1(N.O) SW5.1(N.O) SW6.1(N.O-1) SW6.4(N.O-2) SW7.1(N.C) U4.B1(GND) U5.6(GND) U6.6(GND) U7.6(GND) U8.6(GND)
VBUS: Q4.2(G1) R40.1
VDD: C42.2 C45.2 C48.2 C50.2 Q4.4(S2) R41.1 R52.1 R53.1 R54.2 SB9.1 SB31.1 SW6.6(N.C-2) SW7.3(N.O) U4.A2(VIN) U5.14(VCC) U6.14(VCC) U7.14(VCC) U8.14(VCC)
VDD_PER: R47.2 R48.2 R50.2 R51.2 SB9.2 U4.A1(VOUT)
BOOT/RESET: R54.1 SB43.1 SW5.2(COM) U7.16(COM1)
~{IF_OFF}: SW6.2(COM-1) U5.2(IN_1-2) U5.10(IN_3-4) U6.2(IN_1-2) U6.10(IN_3-4) U7.2(IN_1-2) ; port ~{IF_OFF}
IMCU_BOOT: SB46.2 U7.15(NO1) ; port IMCU_BOOT
IMCU_CTS: TP1.1 U5.3(NO2) ; port IMCU_CTS
IMCU_RTS: TP3.1 U5.15(NO1) ; port IMCU_RTS
IMCU_RxD: TP2.1 U5.11(NO4) ; port IMCU_RxD
IMCU_TxD: TP4.1 U5.7(NO3) ; port IMCU_TxD
~{nRF_ONLY}: R3.1 TP22.1 U4.B2(EN)
OB_RESET: TP7.1 U6.7(NO3) ; port OB_RESET
OB_SWDCLK: TP6.1 U6.3(NO2) ; port OB_SWDCLK
OB_SWDIO: TP5.1 U6.15(NO1) ; port OB_SWDIO
OB_SWO: TP8.1 U6.11(NO4) ; port OB_SWO
P0.04/AIN2: U8.15(NO1) ; port CTS_OPTIONAL
P0.05/AIN3: SB51.1 ; port RTS
P0.06: SB53.1 ; port TxD
P0.07: U8.1(NC1) ; port CTS_DEFAULT
P0.08: SB52.1 ; port RxD
P0.09/NFC1: R43.2 R44.2 ; port P0.09/NFC1
P0.10/NFC2: R45.2 R46.2 ; port P0.10/NFC2
P0.11: U8.5(NC2) ; port BUTTON1_DEFAULT
P0.12: U8.9(NC3) ; port BUTTON2_DEFAULT
P0.13: SB5.1 ; port LED1
P0.14: SB6.1 ; port LED2
P0.15: SB7.1 ; port LED3
P0.16: SB8.1 ; port LED4
P0.18/RESET: SB42.2 SB44.2 SB45.2 SB56.1 ; port RESET
P0.24: SW3.2(COM) ; port BUTTON3
P0.25: SW4.2(COM) ; port BUTTON4
P1.00: SB57.1 ; port SWO
P1.07: U8.3(NO2) ; port BUTTON1_OPTIONAL
SCL: U7.12(COM4) ; port SCL
SDA: U7.8(COM3) ; port SDA
SWDCLK: SB55.1 ; port SWDCLK
SWDIO: SB54.1 ; port SWDIO
TRACE_SW: R4.1 TP23.1 U8.2(IN_1-2) U8.10(IN_3-4)
NetC46_1: C46.1 R44.1 ; port NFC1
NetC47_2: C47.2 R46.1 ; port NFC2
NetLED1_1: LED1.1(C) SB5.2
NetLED1_2: LED1.2(A) R47.1
NetLED2_1: LED2.1(C) SB6.2
NetLED2_2: LED2.2(A) R48.1
NetLED3_1: LED3.1(C) SB7.2
NetLED3_2: LED3.2(A) R50.1
NetLED4_1: LED4.1(C) SB8.2
NetLED4_2: LED4.2(A) R51.1
NetP1_3: SB43.2 SB44.1 U7.4(COM2) ; port RESET_PIN
NetP6_7: R43.1 ; port P0.09
NetP6_8: R45.1 ; port P0.10
NetP28_1: P28.1 U19.5(IN2+)
NetP28_2: P28.2 U19.6(IN2-)
NetP28_3: P28.3 U19.7(OUT2)
NetQ4_3: Q4.3(D2) R26.1 SB31.2 SW6.3(N.C-1) ; port USB_DETECT
NetQ4_5: Q4.5(G2) Q4.6(D1) R41.2
NetR3_2: R3.2 SW6.5(COM-2)
NetR4_2: R4.2 SW7.2(COM)
NetR52_2: R52.2 U7.9(NC3)
NetR53_2: R53.2 U7.13(NC4)
NetR68_1: U7.10(IN_3-4) ; port SHIELD_DETECT
NetSB16_2: U8.7(NO3) ; port BUTTON2_OPTIONAL
NetSB42_1: SB42.1 U7.1(NC1)
NetSB45_1: SB45.1 U7.5(NC2)
NetSB46_1: SB46.1 U7.3(NO2)
NetSB50_1: SB50.1 U8.16(COM1) ; port CTS
NetSB50_2: SB50.2 U5.16(COM1)
NetSB51_2: SB51.2 U5.4(COM2)
NetSB52_2: SB52.2 U5.8(COM3)
NetSB53_2: SB53.2 U5.12(COM4)
NetSB54_2: SB54.2 U6.16(COM1)
NetSB55_2: SB55.2 U6.4(COM2)
NetSB56_2: SB56.2 U6.8(COM3)
NetSB57_2: SB57.2 U6.12(COM4)
NetSW1_2: SW1.2(COM) TP20.1 U8.4(COM2) ; port BUTTON1
NetSW2_2: SW2.2(COM) TP21.1 U8.8(COM3) ; port BUTTON2

Not connected (* = marked no-connect by the designer): U5 1(NC1) 5(NC2) 9(NC3) 13(NC4); U6 1(NC1) 5(NC2) 9(NC3) 13(NC4); U7 7(NO3) 11(NO4); U8 11(NO4) 12(COM4) 13(NC4)

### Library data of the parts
C42 C45 C48 C50 = C0402-100n: as C5 on sheet pca10084_sheet2_nrf52840_mcu
C46 C47 = C0402-300p: Capacitor, NP0, ±5%; Part number IPS: N.A.; Note: 50V; Artikkelnr Noca: 20020004
LED1-LED4 = VS 25C7M5: LED, Green, 0603, 573nm, Vf=2.0V, 24mcd, - 40 to +85°C; Manufacturer: Victory Electronics; Part number IPS: N.A.; Artikkelnr Noca: 13019193
P28 = Pin List 1x3, N.C.: Pin List 1x3, 2.54mm (100mil); Artikkelnr Noca: N.A.
Q4 = DMC3730UFL3-7: as Q2 on sheet pca10084_sheet4_interface_mcu
R3 R4 = R0402-10k: as R22 on sheet pca10084_sheet4_interface_mcu
R26 = R0402-47k: Resistor, ±1%, 0.063W; Part number IPS: N.A.; Note: Chip Res 1%; Artikkelnr Noca: 27049113
R40 = R0402-150k: Resistor, ±1%, 0.063W; Part number IPS: N.A.; Note: Chip Res 1%; Artikkelnr Noca: 27049125
R41 = R0402-1M0: Resistor, ±1%, 0.063W; Part number IPS: 00000006807; Note: Chip Res 1%; Artikkelnr Noca: 27049145
R43 R45 R54 = R0402-N.C.: Not mounted; Note: Chip Res; Artikkelnr Noca: N.A.; Assembly: Not mounted
R44 R46 = R0402-0R: as R1 on sheet pca10084_sheet3_pin_map
R47 R48 R50 R51 = R0402-220: as R20 on sheet pca10084_sheet4_interface_mcu
R52 R53 = R0402-4k7: Resistor, ±1%, 0.063W; Part number IPS: 00000003433; Note: Chip Res 1%; Artikkelnr Noca: 27049089
SB5-SB8 SB42 SB50-SB57 = Solderbridge Shorted: as SB1 on sheet pca10084_sheet2_nrf52840_mcu
SB9 SB31 SB43-SB46 = Solderbridge: Artikkelnr Noca: N.A.
SW1-SW5 = Switch-PB-6.2x6.3mm-SMD: Tactile Switch, SPNO, SMD, 160gf, 6.2x6.3x2.5mm; Manufacturer: Dailywell; Manufacturer Part Number: TS604VM1-025BR-R; Part number IPS: 00000007812; Artikkelnr Noca: 50019106
SW6 = MKH-22D14-G2-B: Slide Switch DPDT; Manufacturer: Dailywell; Part number IPS: N.A.; Artikkelnr Noca: 50019112
SW7 = CJS-1200TA: SMD slide Switch (ON-ON); Manufacturer: Copal Electronics Inc; Part number IPS: N.A.; Artikkelnr Noca: 50019068
TP1-TP8 TP20-TP23 = TP_SMD_Ø1.0MM: 1.0mm circular SMD testpad; Manufacturer: Nordic Semiconductor; Artikkelnr Noca: N.A.
U4 = SC728CSTRT: Semtech, 2A Low Vin, Very Low Ron, Load Switch, 4DSBGA; Manufacturer: Semtech Corporation; Part number IPS: N.A.; Artikkelnr Noca: 15070081
U5-U8 = FSA2466UMX: Data / Audio Low-Voltage Dual DPDT Analog Switch; Manufacturer: Fairchild Semiconductor; Part number IPS: N.A.; Artikkelnr Noca: 15070069
U19 = TS27L2IPT: Precision very low power CMOS dual operational amplifier; Manufacturer: STMicroelectronics; Part number IPS: N.A.; Artikkelnr Noca: 17010019

## Sheet pca10084_sheet6_connectors.SchDoc: PCA10084 - Connectors
size A3; Organization: Nordic Semiconductor; DocumentNumber: 6; Revision: 0.7.0; SheetNumber: 6; SheetTotal: 8; Author: GETR; CompanyName: Nordic Semiconductor; DrawnBy: GETR
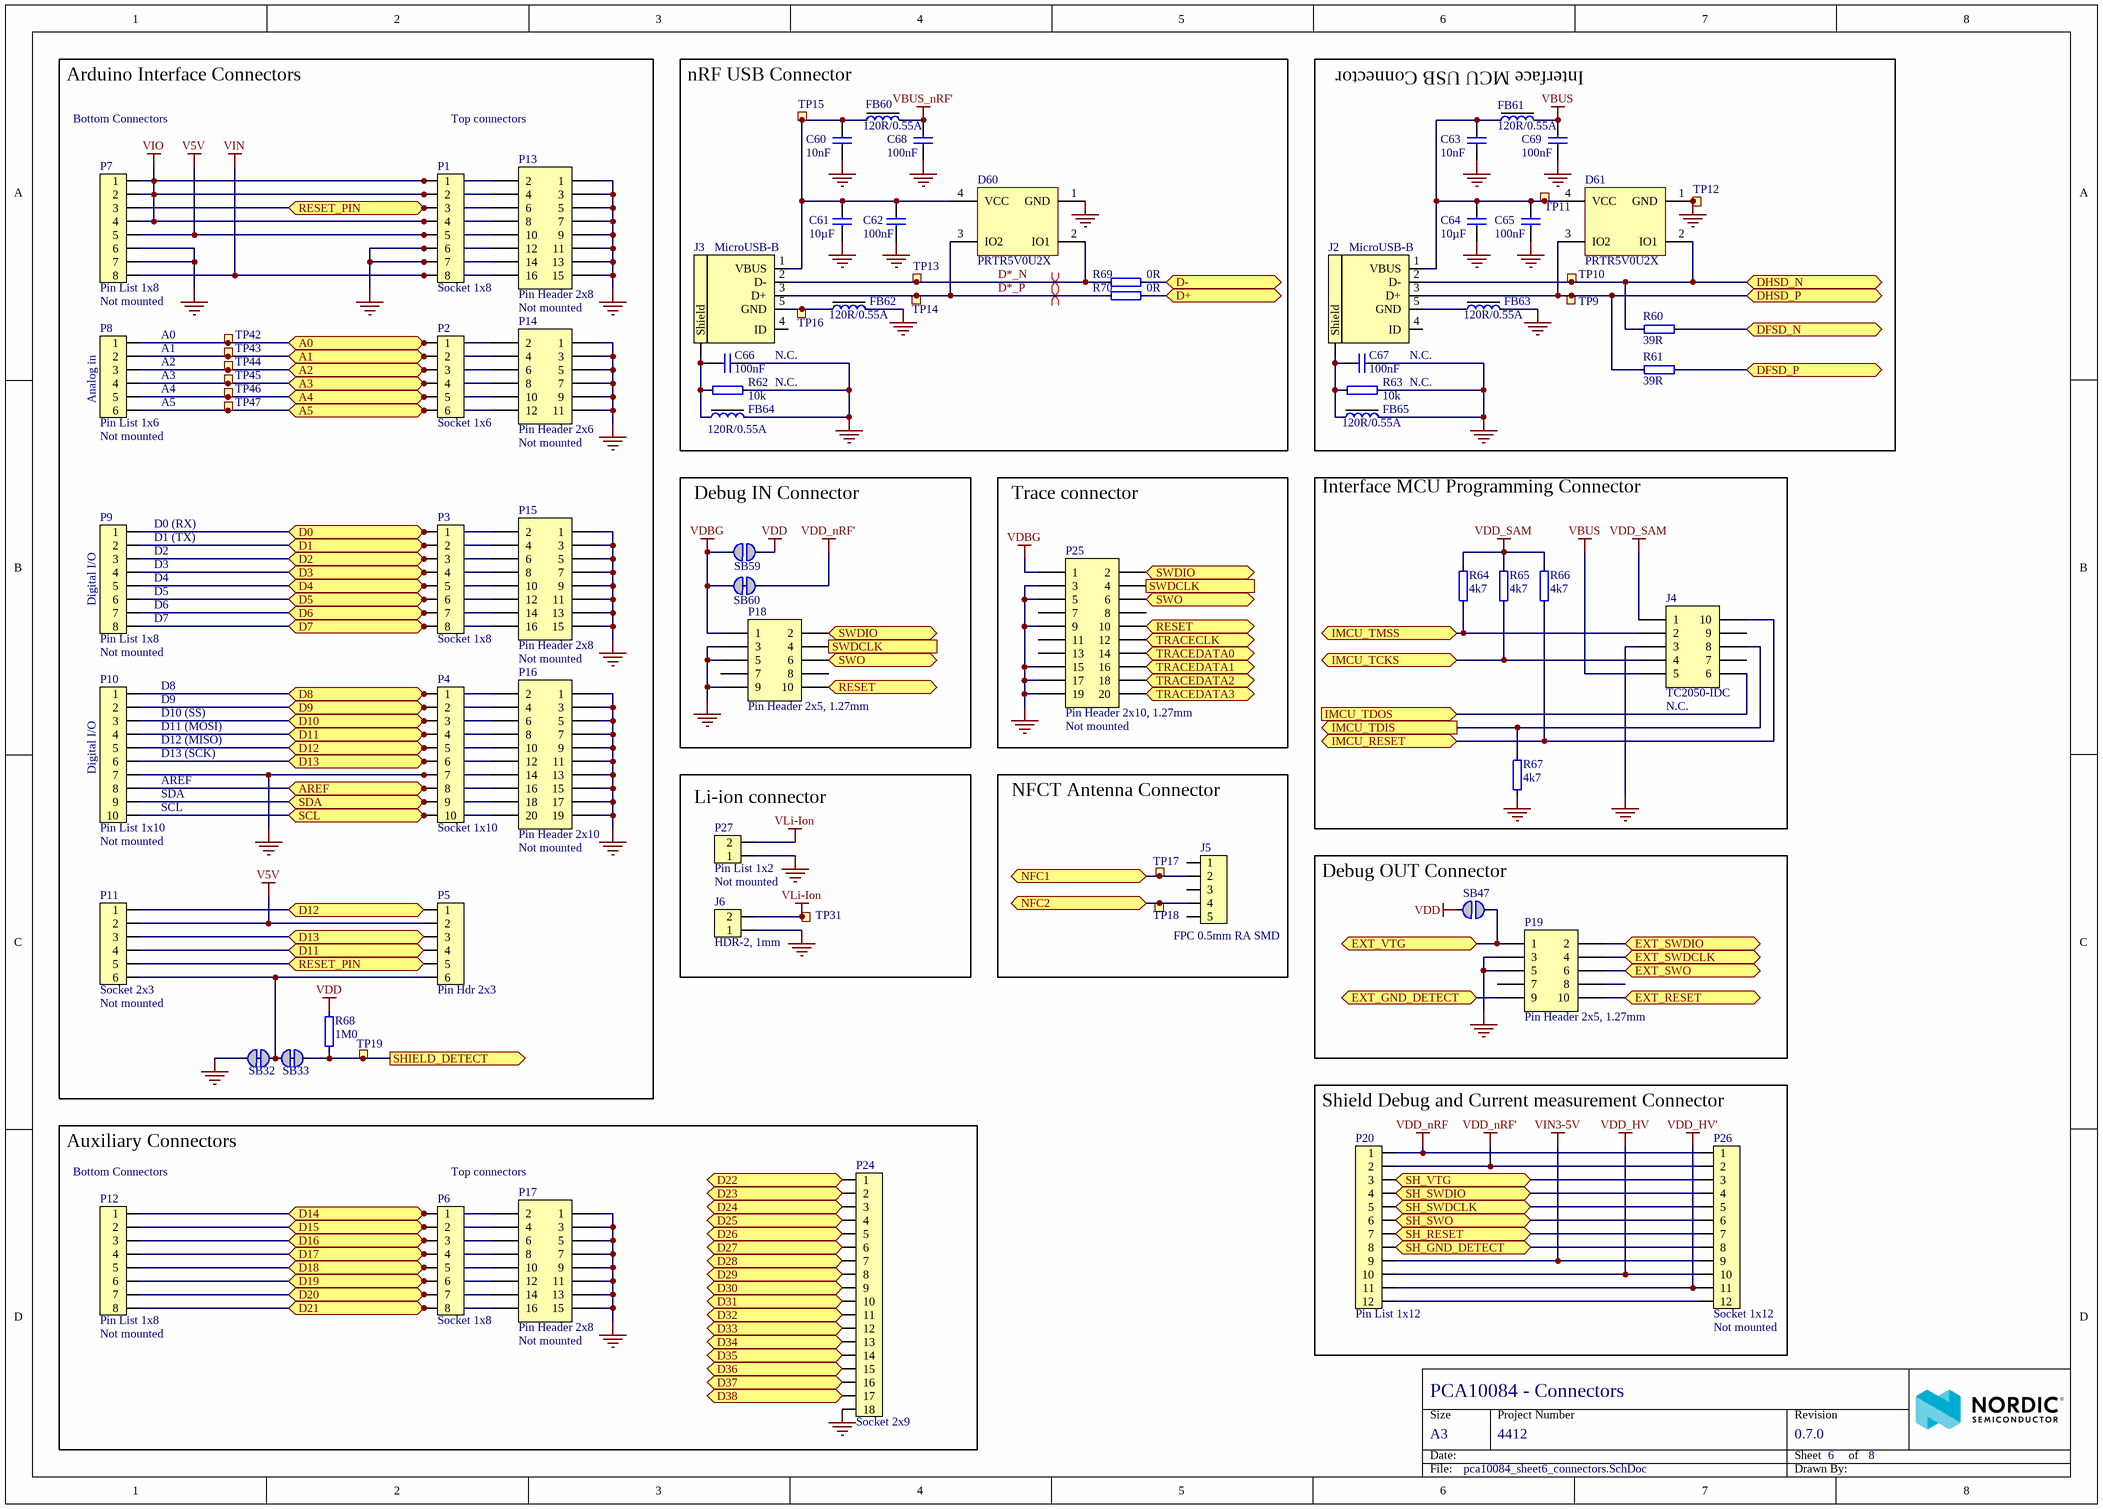
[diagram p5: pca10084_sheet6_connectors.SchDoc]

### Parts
C60  10nF  [CAPC1005X04L]
C61  10µF  [CAPC1608X06L]
C62  100nF  [CAPC1005X04L]
C63  10nF  [CAPC1005X04L]
C64  10µF  [CAPC1608X06L]
C65  100nF  [CAPC1005X04L]
C66  100nF  Assembly: N.C.  [CAPC1005X04L]
C67  100nF  Assembly: N.C.  [CAPC1005X04L]
C68  100nF  [CAPC1005X04L]
C69  100nF  [CAPC1005X04L]
D60  PRTR5V0U2X  [SOT190P230X110-4L]
D61  PRTR5V0U2X  [SOT190P230X110-4L]
FB60  120R/0.55A  [INDC1005X04L]
FB61  120R/0.55A  [INDC1005X04L]
FB62  120R/0.55A  [INDC1005X04L]
FB63  120R/0.55A  [INDC1005X04L]
FB64  120R/0.55A  [INDC1005X04L]
FB65  120R/0.55A  [INDC1005X04L]
J2  MicroUSB-B  [USB-Micro-B-RA-SMD-PiP]
J3  MicroUSB-B  [USB-Micro-B-RA-SMD-PiP]
J4  TC2050-IDC  Assembly: N.C.  [TC2050-IDC-NLFP]
J5  FPC 0.5mm RA SMD  [FPC_05P-0.5mm-RA-SMD]
J6  HDR-2, 1mm  [SM02B-SRSS-TB]
P1  Socket 1x8  [SOCKET_1x8_SMD]
P2  Socket 1x6  [SOCKET_1x6_SMD]
P3  Socket 1x8  [SOCKET_1x8_SMD]
P4  Socket 1x10  [SOCKET_1x10_SMD]
P5  Pin Hdr 2x3  [HDR_2x3-SMD]
P6  Socket 1x8  [SOCKET_1x8_SMD]
P7  Pin List 1x8  Assembly: Not mounted  [LIST_1x8_SMD-NC]
P8  Pin List 1x6  Assembly: Not mounted  [LIST_1x6_SMD-NC]
P9  Pin List 1x8  Assembly: Not mounted  [LIST_1x8_SMD-NC]
P10  Pin List 1x10  Assembly: Not mounted  [LIST_1x10_SMD-NC]
P11  Socket 2x3  Assembly: Not mounted  [SOCKET_2x3_SMD-2.54mm-bottom-NC]
P12  Pin List 1x8  Assembly: Not mounted  [LIST_1x8_SMD-NC]
P13  Pin Header 2x8  Assembly: Not mounted  [HDR_2x8-NC]
P14  Pin Header 2x6  Assembly: Not mounted  [HDR_2x6-NC]
P15  Pin Header 2x8  Assembly: Not mounted  [HDR_2x8-NC]
P16  Pin Header 2x10  Assembly: Not mounted  [HDR_2x10-NC]
P17  Pin Header 2x8  Assembly: Not mounted  [HDR_2x8-NC]
P18  Pin Header 2x5, 1.27mm  [HDR_2x5-SMD-1.27mm-K]
P19  Pin Header 2x5, 1.27mm  [HDR_2x5-SMD-1.27mm-K]
P20  Pin List 1x12  [LIST_1x12_SMD]
P24  Socket 2x9  [SOCKET_2x9_SMD-2.54mm]
P25  Pin Header 2x10, 1.27mm  Assembly: Not mounted  [HDR_2x10-SMD-1.27mm-NC]
P26  Socket 1x12  Assembly: Not mounted  [LIST_1x12_SMD-NC]
P27  Pin List 1x2  Assembly: Not mounted  [LIST_1x2-NC]
R60  39R  [RESC1005X04L]
R61  39R  [RESC1005X04L]
R62  10k  Assembly: N.C.  [RESC1005X04L]
R63  10k  Assembly: N.C.  [RESC1005X04L]
R64  4k7  [RESC1005X04L]
R65  4k7  [RESC1005X04L]
R66  4k7  [RESC1005X04L]
R67  4k7  [RESC1005X04L]
R68  1M0  [RESC1005X04L]
R69  0R  [RESC1005X04L]
R70  0R  [RESC1005X04L]
SB32  Solderbridge  [Solderbridge_Shorted]  (value not drawn)  (net tie, no BOM)
SB33  Solderbridge  [Solderbridge_Shorted]  (value not drawn)  (net tie, no BOM)
SB47  Solderbridge  [Solderbridge]  (value not drawn)  (no BOM)
SB59  Solderbridge  [Solderbridge]  (value not drawn)  (no BOM)
SB60  Solderbridge  [Solderbridge_Shorted]  (value not drawn)  (net tie, no BOM)
TP9  Ø1.0mm,SMD  [TP_SMD_Ø1.0mm]  (value not drawn)  (no BOM)
TP10  Ø1.0mm,SMD  [TP_SMD_Ø1.0mm]  (value not drawn)  (no BOM)
TP11  Ø1.0mm,SMD  [TP_SMD_Ø1.0mm]  (value not drawn)  (no BOM)
TP12  Ø1.0mm,SMD  [TP_SMD_Ø1.0mm]  (value not drawn)  (no BOM)
TP13  Ø1.5mm,SMD  [TP_SMD_Ø1.5mm]  (value not drawn)  (no BOM)
TP14  Ø1.5mm,SMD  [TP_SMD_Ø1.5mm]  (value not drawn)  (no BOM)
TP15  Ø1.5mm,SMD  [TP_SMD_Ø1.5mm]  (value not drawn)  (no BOM)
TP16  Ø1.5mm,SMD  [TP_SMD_Ø1.5mm]  (value not drawn)  (no BOM)
TP17  Ø1.0mm,SMD  [TP_SMD_Ø1.0mm]  (value not drawn)  (no BOM)
TP18  Ø1.0mm,SMD  [TP_SMD_Ø1.0mm]  (value not drawn)  (no BOM)
TP19  Ø1.0mm,SMD  [TP_SMD_Ø1.0mm]  (value not drawn)  (no BOM)
TP31  Ø1.0mm,SMD  [TP_SMD_Ø1.0mm]  (value not drawn)  (no BOM)
TP42  Ø1.0mm,SMD  [TP_SMD_Ø1.0mm]  (value not drawn)  (no BOM)
TP43  Ø1.0mm,SMD  [TP_SMD_Ø1.0mm]  (value not drawn)  (no BOM)
TP44  Ø1.0mm,SMD  [TP_SMD_Ø1.0mm]  (value not drawn)  (no BOM)
TP45  Ø1.0mm,SMD  [TP_SMD_Ø1.0mm]  (value not drawn)  (no BOM)
TP46  Ø1.0mm,SMD  [TP_SMD_Ø1.0mm]  (value not drawn)  (no BOM)
TP47  Ø1.0mm,SMD  [TP_SMD_Ø1.0mm]  (value not drawn)  (no BOM)

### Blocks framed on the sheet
Arduino Interface Connectors: P1-P5 P7-P11 P13-P16 R68 SB32 SB33 TP19 TP42-TP47
nRF USB Connector: C60-C62 C66 C68 D60 FB60 FB62 FB64 J3 R62 R69 R70 TP13-TP16
Interface MCU USB Connector: C63-C65 C67 C69 D61 FB61 FB63 FB65 J2 R60 R61 R63 TP9-TP12
Debug IN Connector: P18 SB59 SB60
Trace connector: P25
Interface MCU Programming Connector: J4 R64-R67
Li-ion connector: J6 P27 TP31
NFCT Antenna Connector: J5 TP17 TP18
Debug OUT Connector: P19 SB47
Shield Debug and Current measurement Connector: P20 P26
Auxiliary Connectors: P6 P12 P17 P24

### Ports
A0 (bidir), A1 (bidir), A2 (bidir), A3 (bidir), A4 (bidir), A5 (bidir), AREF (bidir), D0 (bidir), D1 (bidir), D2 (bidir), D3 (bidir), D4 (bidir), D5 (bidir), D6 (bidir), D7 (bidir), D8 (bidir), D9 (bidir), D10 (bidir), D11 (bidir), D12 (bidir), D13 (bidir), D14 (bidir), D15 (bidir), D16 (bidir), D17 (bidir), D18 (bidir), D19 (bidir), D20 (bidir), D21 (bidir), D22 (bidir), D23 (bidir), D24 (bidir), D25 (bidir), D26 (bidir), D27 (bidir), D28 (bidir), D29 (bidir), D30 (bidir), D31 (bidir), D32 (bidir), D33 (bidir), D34 (bidir), D35 (bidir), D36 (bidir), D37 (bidir), D38 (bidir), D+ (bidir), D- (bidir), DFSD_N (bidir), DFSD_P (bidir), DHSD_N (bidir), DHSD_P (bidir), EXT_GND_DETECT (bidir), EXT_RESET (bidir), EXT_SWDCLK (bidir), EXT_SWDIO (bidir), EXT_SWO (bidir), EXT_VTG (bidir), IMCU_RESET (bidir), IMCU_TCKS (bidir), IMCU_TDIS (out), IMCU_TDOS (in), IMCU_TMSS (bidir), NFC1 (bidir), NFC2 (bidir), RESET (bidir), RESET_PIN (bidir), SCL (bidir), SDA (bidir), SH_GND_DETECT (bidir), SH_RESET (bidir), SH_SWDCLK (bidir), SH_SWDIO (bidir), SH_SWO (bidir), SH_VTG (bidir), SHIELD_DETECT (out), SWDCLK (out), SWDIO (bidir), SWO (bidir), TRACECLK (bidir), TRACEDATA0 (bidir), TRACEDATA1 (bidir), TRACEDATA2 (bidir), TRACEDATA3 (bidir)

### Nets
GND: C60.1 C61.1 C62.1 C63.2 C64.1 C65.1 C66.1 C67.1 C68.1 C69.1 D60.1(GND) D61.1(GND) FB62.2 FB63.2 FB64.2 FB65.2 J4.3 J6.1 P1.6 P1.7 P4.7 P7.6 P7.7 P10.7 P13.1 P13.3 P13.5 P13.7 P13.9 P13.11 P13.12 P13.13 P13.14 P13.15 P14.1 P14.3 P14.5 P14.7 P14.9 P14.11 P15.1 P15.3 P15.5 P15.7 P15.9 P15.11 P15.13 P15.15 P16.1 P16.3 P16.5 P16.7 P16.9 P16.11 P16.13 P16.14 P16.15 P16.17 P16.19 P17.1 P17.3 P17.5 P17.7 P17.9 P17.11 P17.13 P17.15 P18.3 P18.5 P18.9 P19.3 P19.5 P24.18 P25.3 P25.5 P25.9 P25.15 P25.17 P25.19 P27.1 R62.1 R63.1 R67.2 SB32.1 TP12.1
V5V: P1.5 P5.2 P7.5 P11.2 P13.10
VBUS: C69.2 FB61.2 J4.5
VBUS_nRF': C68.2 FB60.2
VDBG: P18.1 P25.1 SB59.1 SB60.1
VDD: R68.2 SB47.1 SB59.2
VDD_HV: P20.10 P26.10
VDD_HV': P20.11 P26.11
VDD_nRF: P20.1 P26.1
VDD_nRF': P20.2 P26.2 SB60.2
VDD_SAM: J4.1 R64.2 R65.2 R66.2
VIN: P1.8 P7.8 P13.16
VIN3-5V: P20.9 P26.9
VIO: P1.1 P1.2 P1.4 P7.1 P7.2 P7.4 P13.2 P13.4 P13.8
VLi-Ion: J6.2 P27.2 TP31.1
D*_N: D60.2(IO1) J3.2(D-) R69.2 TP13.1
D*_P: D60.3(IO2) J3.3(D+) R70.2 TP14.1
D_N: R69.1 ; port D-
D_P: R70.1 ; port D+
DFSD_N: R60.1 ; port DFSD_N
DFSD_P: R61.1 ; port DFSD_P
DHSD_N: D61.2(IO1) J2.2(D-) R60.2 TP10.1 ; port DHSD_N
DHSD_P: D61.3(IO2) J2.3(D+) R61.2 TP9.1 ; port DHSD_P
EXT_GND_DETECT: P19.9 ; port EXT_GND_DETECT
EXT_RESET: P19.10 ; port EXT_RESET
EXT_SWDCLK: P19.4 ; port EXT_SWDCLK
EXT_SWDIO: P19.2 ; port EXT_SWDIO
EXT_SWO: P19.6 ; port EXT_SWO
EXT_VTG: P19.1 SB47.2 ; port EXT_VTG
IMCU_RESET: J4.10 R66.1 ; port IMCU_RESET
IMCU_TCKS: J4.4 R65.1 ; port IMCU_TCKS
IMCU_TDIS: J4.8 R67.1 ; port IMCU_TDIS
IMCU_TDOS: J4.6 ; port IMCU_TDOS
IMCU_TMSS: J4.2 R64.1 ; port IMCU_TMSS
P0.00: P6.1 P12.1 P17.2 ; port D14
P0.01: P6.2 P12.2 P17.4 ; port D15
P0.02/AIN0: P4.8 P10.8 P16.16 ; port AREF
P0.03/AIN1: P2.1 P8.1 P14.2 TP42.1 ; port A0
P0.04/AIN2: P2.2 P8.2 P14.4 TP43.1 ; port A1
P0.05/AIN3: P6.3 P12.3 P17.6 ; port D16
P0.06: P6.4 P12.4 P17.8 ; port D17
P0.07: P6.5 P12.5 P17.10 P25.12 ; port D18, port TRACECLK
P0.08: P6.6 P12.6 P17.12 ; port D19
P0.11: P24.1 P25.18 ; port D22, port TRACEDATA2
P0.12: P24.2 P25.16 ; port D23, port TRACEDATA1
P0.13: P24.3 ; port D24
P0.14: P24.4 ; port D25
P0.15: P24.5 ; port D26
P0.16: P24.6 ; port D27
P0.18/RESET: P18.10 P24.8 P25.10 ; port RESET, port D29
P0.24: P24.14 ; port D35
P0.25: P24.15 ; port D36
P0.28/AIN4: P2.3 P8.3 P14.6 TP44.1 ; port A2
P0.29/AIN5: P2.4 P8.4 P14.8 TP45.1 ; port A3
P0.30/AIN6: P2.5 P8.5 P14.10 TP46.1 ; port A4
P1.00: P18.6 P24.16 P25.6 P25.14 ; port SWO, port D37, port TRACEDATA0
P1.01: P3.1 P9.1 P15.2 ; port D0
P1.02: P3.2 P9.2 P15.4 ; port D1
P1.03: P3.3 P9.3 P15.6 ; port D2
P1.04: P3.4 P9.4 P15.8 ; port D3
P1.05: P3.5 P9.5 P15.10 ; port D4
P1.06: P3.6 P9.6 P15.12 ; port D5
P1.07: P3.7 P9.7 P15.14 ; port D6
P1.09: P24.17 P25.20 ; port D38, port TRACEDATA3
P1.10: P4.1 P10.1 P16.2 ; port D8
P1.11: P4.2 P10.2 P16.4 ; port D9
P1.12: P4.3 P10.3 P16.6 ; port D10
P1.13: P4.4 P5.4 P10.4 P11.4 P16.8 ; port D11
P1.14: P4.5 P5.1 P10.5 P11.1 P16.10 ; port D12
P1.15: P4.6 P5.3 P10.6 P11.3 P16.12 ; port D13
SCL: P4.10 P10.10 P16.20 ; port SCL
SDA: P4.9 P10.9 P16.18 ; port SDA
SH_GND_DETECT: P20.8 P26.8 ; port SH_GND_DETECT
SH_RESET: P20.7 P26.7 ; port SH_RESET
SH_SWDCLK: P20.5 P26.5 ; port SH_SWDCLK
SH_SWDIO: P20.4 P26.4 ; port SH_SWDIO
SH_SWO: P20.6 P26.6 ; port SH_SWO
SH_VTG: P20.3 P26.3 ; port SH_VTG
SWDCLK: P18.4 P25.4 ; port SWDCLK
SWDIO: P18.2 P25.2 ; port SWDIO
NetC46_1: J5.2 TP17.1 ; port NFC1
NetC47_2: J5.4 TP18.1 ; port NFC2
NetC60_2: C60.2 C61.2 C62.2 D60.4(VCC) FB60.1 J3.1(VBUS) TP15.1
NetC63_1: C63.1 C64.2 C65.2 D61.4(VCC) FB61.1 J2.1(VBUS) TP11.1
NetC66_2: C66.2 FB64.1 J3.6(Shield) R62.2
NetC67_2: C67.2 FB65.1 J2.6(Shield) R63.2
NetFB62_1: FB62.1 J3.5(GND) TP16.1
NetFB63_1: FB63.1 J2.5(GND)
NetP1_3: P1.3 P5.5 P7.3 P11.5 P13.6 ; port RESET_PIN
NetP2_6: P2.6 P8.6 P14.12 TP47.1 ; port A5
NetP3_8: P3.8 P9.8 P15.16 ; port D7
NetP5_6: P5.6 P11.6 SB32.2 SB33.1
NetP6_7: P6.7 P12.7 P17.14 ; port D20
NetP6_8: P6.8 P12.8 P17.16 ; port D21
NetP20_12: P20.12 P26.12
NetP24_7: P24.7 ; port D28
NetP24_9: P24.9 ; port D30
NetP24_10: P24.10 ; port D31
NetP24_11: P24.11 ; port D32
NetP24_12: P24.12 ; port D33
NetP24_13: P24.13 ; port D34
NetR68_1: R68.1 SB33.2 TP19.1 ; port SHIELD_DETECT

Not connected (* = marked no-connect by the designer): J2 4(ID); J3 4(ID); J4 7 9; J5 1 3 5; P18 7 8; P19 7 8; P25 7 8 11 13

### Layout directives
differential pair: D*_N, D*_P

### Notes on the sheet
- Bottom Connectors
- Top connectors
- (near P8) A0
- (near P8) A1
- (near P8) A2
- (near P8) A3
- (near P8) Analog in
- (near P8) A4
- (near P8) A5
- (near P9) D0 (RX)
- (near P9) D1 (TX)
- (near P9) D2
- (near P9) D3
- (near P9) D4
- (near P9) Digital I/O
- (near P9) D5
- (near P9) D6
- (near P9) D7
- (near P10) D8
- (near P10) D9
- (near P10) D10 (SS)
- (near P10) Digital I/O
- (near P10) AREF
- (near P10) D11 (MOSI)
- (near P10) D12 (MISO)
- (near P10) D13 (SCK)
- (near P10) SDA
- (near P10) SCL
- (near P12) Bottom Connectors

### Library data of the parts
C60 C63 = C0402-10n: as C44 on sheet pca10084_sheet4_interface_mcu
C61 C64 = C0603-10µ: as C38 on sheet pca10084_sheet4_interface_mcu
C62 C65-C69 = C0402-100n: as C5 on sheet pca10084_sheet2_nrf52840_mcu
D60 D61 = PRTR5V0U2X: Ultra low capacitance double rail-to-rail ESD protection diode; Manufacturer: NXP; Part number IPS: 00000009951; Artikkelnr Noca: 10069015
FB60-FB65 = FB0402-120R@100M-500mA: Ferrite Bead, 120 Ohm @ 100MHz, 500mA, 250 mOhm Max; Manufacturer: Murata; Manufacturer Part Number: BLM15AG121SN1D; Part number IPS: N.A.; Note: Chip EMIFIL Inductor Type Chip Ferrite Bead; Artikkelnr Noca: 33029317
J2 J3 = USB-Micro-B-RA-SMD-PiP: MicroUSB-B-SMT; Manufacturer: Allen Creations Corp.; Manufacturer Part Number: AJU55-BS2111-L; Part number IPS: 00000007790; Artikkelnr Noca: 55029020
J4 = TC2050-IDC-NLFP: CBL PLUG-OF-NAILS 10-PIN; Manufacturer: Tag-Connect LLC; Artikkelnr Noca: N.A.
J5 = FPC_05P-0.5mm-RA-SMD: 0.5mm FPC, 5P,Right Angle SMT,Double Contact,H=1.2mm,White, Tin plated; Manufacturer: W-CON; Manufacturer Part Number: 5141-05RZDNWR01; Part number IPS: 00000007792; Artikkelnr Noca: 55010020
J6 = SM02B-SRSS-TB: 1.0mm pitch connector side entry SMD; Manufacturer: JST; Manufacturer Part Number: SM02B-SRSS-TB(LF)(SN); Part number IPS: 00000007791; Note: JST, Header; Artikkelnr Noca: 55010030
P1 P3 P6 = Socket 1x8 SMD: Socket 1x8, 2.54mm (100mil), SMD; Manufacturer: W-CON; Manufacturer Part Number: 2171-108MS0CUNR1; Part number IPS: N.A.; Artikkelnr Noca: 55030002
P2 = Socket 1x6 SMD: Socket 1x6, 2.54mm (100mil), SMD; Manufacturer: W-CON; Manufacturer Part Number: 2171-106MS0CUNR1; Part number IPS: N.A.; Artikkelnr Noca: 55030001
P4 = Socket 1x10 SMD: Socket 1x10, 2.54mm (100mil), SMD; Manufacturer: W-CON; Manufacturer Part Number: 2171-110MS0CUNR1; Part number IPS: N.A.; Artikkelnr Noca: 55030004
P5 = Pin Header 2x3 SMD: Pin Header 2x3, 2.54mm (100mil) SMD; Manufacturer: W-CON; Manufacturer Part Number: 1125-1203S0M116R1; Part number IPS: N.A.; Artikkelnr Noca: 55010007
P7 P9 P12 = Pin List 1x8 SMD, N.C.: Pin List 1x8, 2.54mm (100mil), SMD; Manufacturer: W-CON; Manufacturer Part Number: 1125-1108S0M116R2; Part number IPS: N.A.; Artikkelnr Noca: 55010006
P8 = Pin List 1x6 SMD, N.C.: Pin List 1x6, 2.54mm (100mil), SMD; Manufacturer: W-CON; Manufacturer Part Number: 1125-1106S0M116R2; Part number IPS: N.A.; Artikkelnr Noca: 55010026
P10 = Pin List 1x10 SMD, N.C.: Pin List 1x10, 2.54mm (100mil), SMD; Manufacturer: W-CON; Manufacturer Part Number: 1125-1110S0M116R2; Part number IPS: N.A.; Artikkelnr Noca: 55010028
P11 = Socket 2x3 SMD Bottom, N.C.: Socket 2x3, 2.54mm (100mil), SMD; Manufacturer: W-CON; Manufacturer Part Number: 2171-203MS0CUNR1; Part number IPS: N.A.; Artikkelnr Noca: 55030010
P13 P15 P17 = Pin Header 2x8, N.C.: Pin Header 2x8, 2.54mm (100mil); Artikkelnr Noca: N.A.
P14 = Pin Header 2x6, N.C.: Pin Header 2x6, 2.54mm (100mil); Artikkelnr Noca: N.A.
P16 = Pin Header 2x10, N.C.: Pin Header 2x10, 2.54mm (100mil); Artikkelnr Noca: N.A.
P18 P19 = Pin Header 2x5 SMD, 1.27mm, KS: Pin Header 2x5, 1.27mm (50mil), SMD, Keying Shroud; Manufacturer: W-CON; Manufacturer Part Number: 3132-10MS0BK00R1; Part number IPS: N.A.; Artikkelnr Noca: 55010009
P20 = Pin List 1x12 SMD: Pin List 1x12, 2.54mm (100mil), SMD; Manufacturer: W-CON; Manufacturer Part Number: 1125-1112S0M116R2; Part number IPS: N.A.; Artikkelnr Noca: 55019293
P24 = Socket 2x9 SMD: Socket 2x9, 2.54mm (100mil), SMD; Manufacturer: W-CON; Manufacturer Part Number: 2171-209MS0CUNR1; Part number IPS: N.A.; Artikkelnr Noca: 55030011
P25 = Pin Header 2x10 SMD, 1.27mm, KS, N.C.: Pin Header 2x10, 1.27mm (50mil), SMD, Keying Shroud; Manufacturer: W-CON; Manufacturer Part Number: 3132-20MS0BK00R1; Artikkelnr Noca: N.A.
P26 = Socket 1x12 SMD, N.C.: Socket 1x12, 2.54mm (100mil), SMD; Manufacturer: W-CON; Manufacturer Part Number: 2171-112MS0CUNR1; Artikkelnr Noca: N.A.
P27 = Pin List 1x2, N.C.: Pin List 1x2, 2.54mm (100mil); Artikkelnr Noca: N.A.
R60 R61 = R0402-39R: Resistor, ±1%, 0.063W; Part number IPS: 00000000821; Note: Chip Res 1%; Artikkelnr Noca: 27049039
R62 R63 = R0402-10k: as R22 on sheet pca10084_sheet4_interface_mcu
R64-R67 = R0402-4k7: as R52 on sheet pca10084_sheet5_misc
R68 = R0402-1M0: as R41 on sheet pca10084_sheet5_misc
R69 R70 = R0402-0R: as R1 on sheet pca10084_sheet3_pin_map
SB32 SB33 SB60 = Solderbridge Shorted: as SB1 on sheet pca10084_sheet2_nrf52840_mcu
SB47 SB59 = Solderbridge: Artikkelnr Noca: N.A.
TP9-TP12 TP17-TP19 TP31 TP42-TP47 = TP_SMD_Ø1.0MM: as TP1 on sheet pca10084_sheet5_misc
TP13-TP16 = TP_SMD_Ø1.5MM: 1.0mm circular SMD testpad; Manufacturer: Nordic Semiconductor; Artikkelnr Noca: N.A.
